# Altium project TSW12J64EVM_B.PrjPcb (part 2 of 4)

## Sheet TSW12J64EVM_B_4_ADC_IO.SchDoc
size 431 x 279 mm; Date: Not shown in title block; ApprovedBy: Not shown in title block; CheckedBy: Not shown in title block; Author: Not shown in title block; CompanyName: Not shown in title block; Engineer: Not shown in title block; Organization: Not shown in title block; Address1: Not shown in title block; Address2: Not shown in title block; Address3: Not shown in title block; Address4: Not shown in title block; DocumentNumber: 4; Revision: Use project parameter SCH_Rev; SheetNumber: 4; SheetTotal: 11; PageSetup: Record=PageOptions¦CenterHorizontal=True¦CenterVertical=True¦PrintScale=1.32¦XCorrection=1.00¦YCorrection=1.00¦PrintKind=0¦BorderSize=5000000¦LeftOffset=0¦BottomOffset=0¦Orientation=2¦PaperLength=1000¦PaperWidth=1000¦Scale=100¦PaperSource=15¦PrintQuality=600¦MediaType=1¦DitherType=10¦PaperKind=Letter¦PrintScaleMode=1
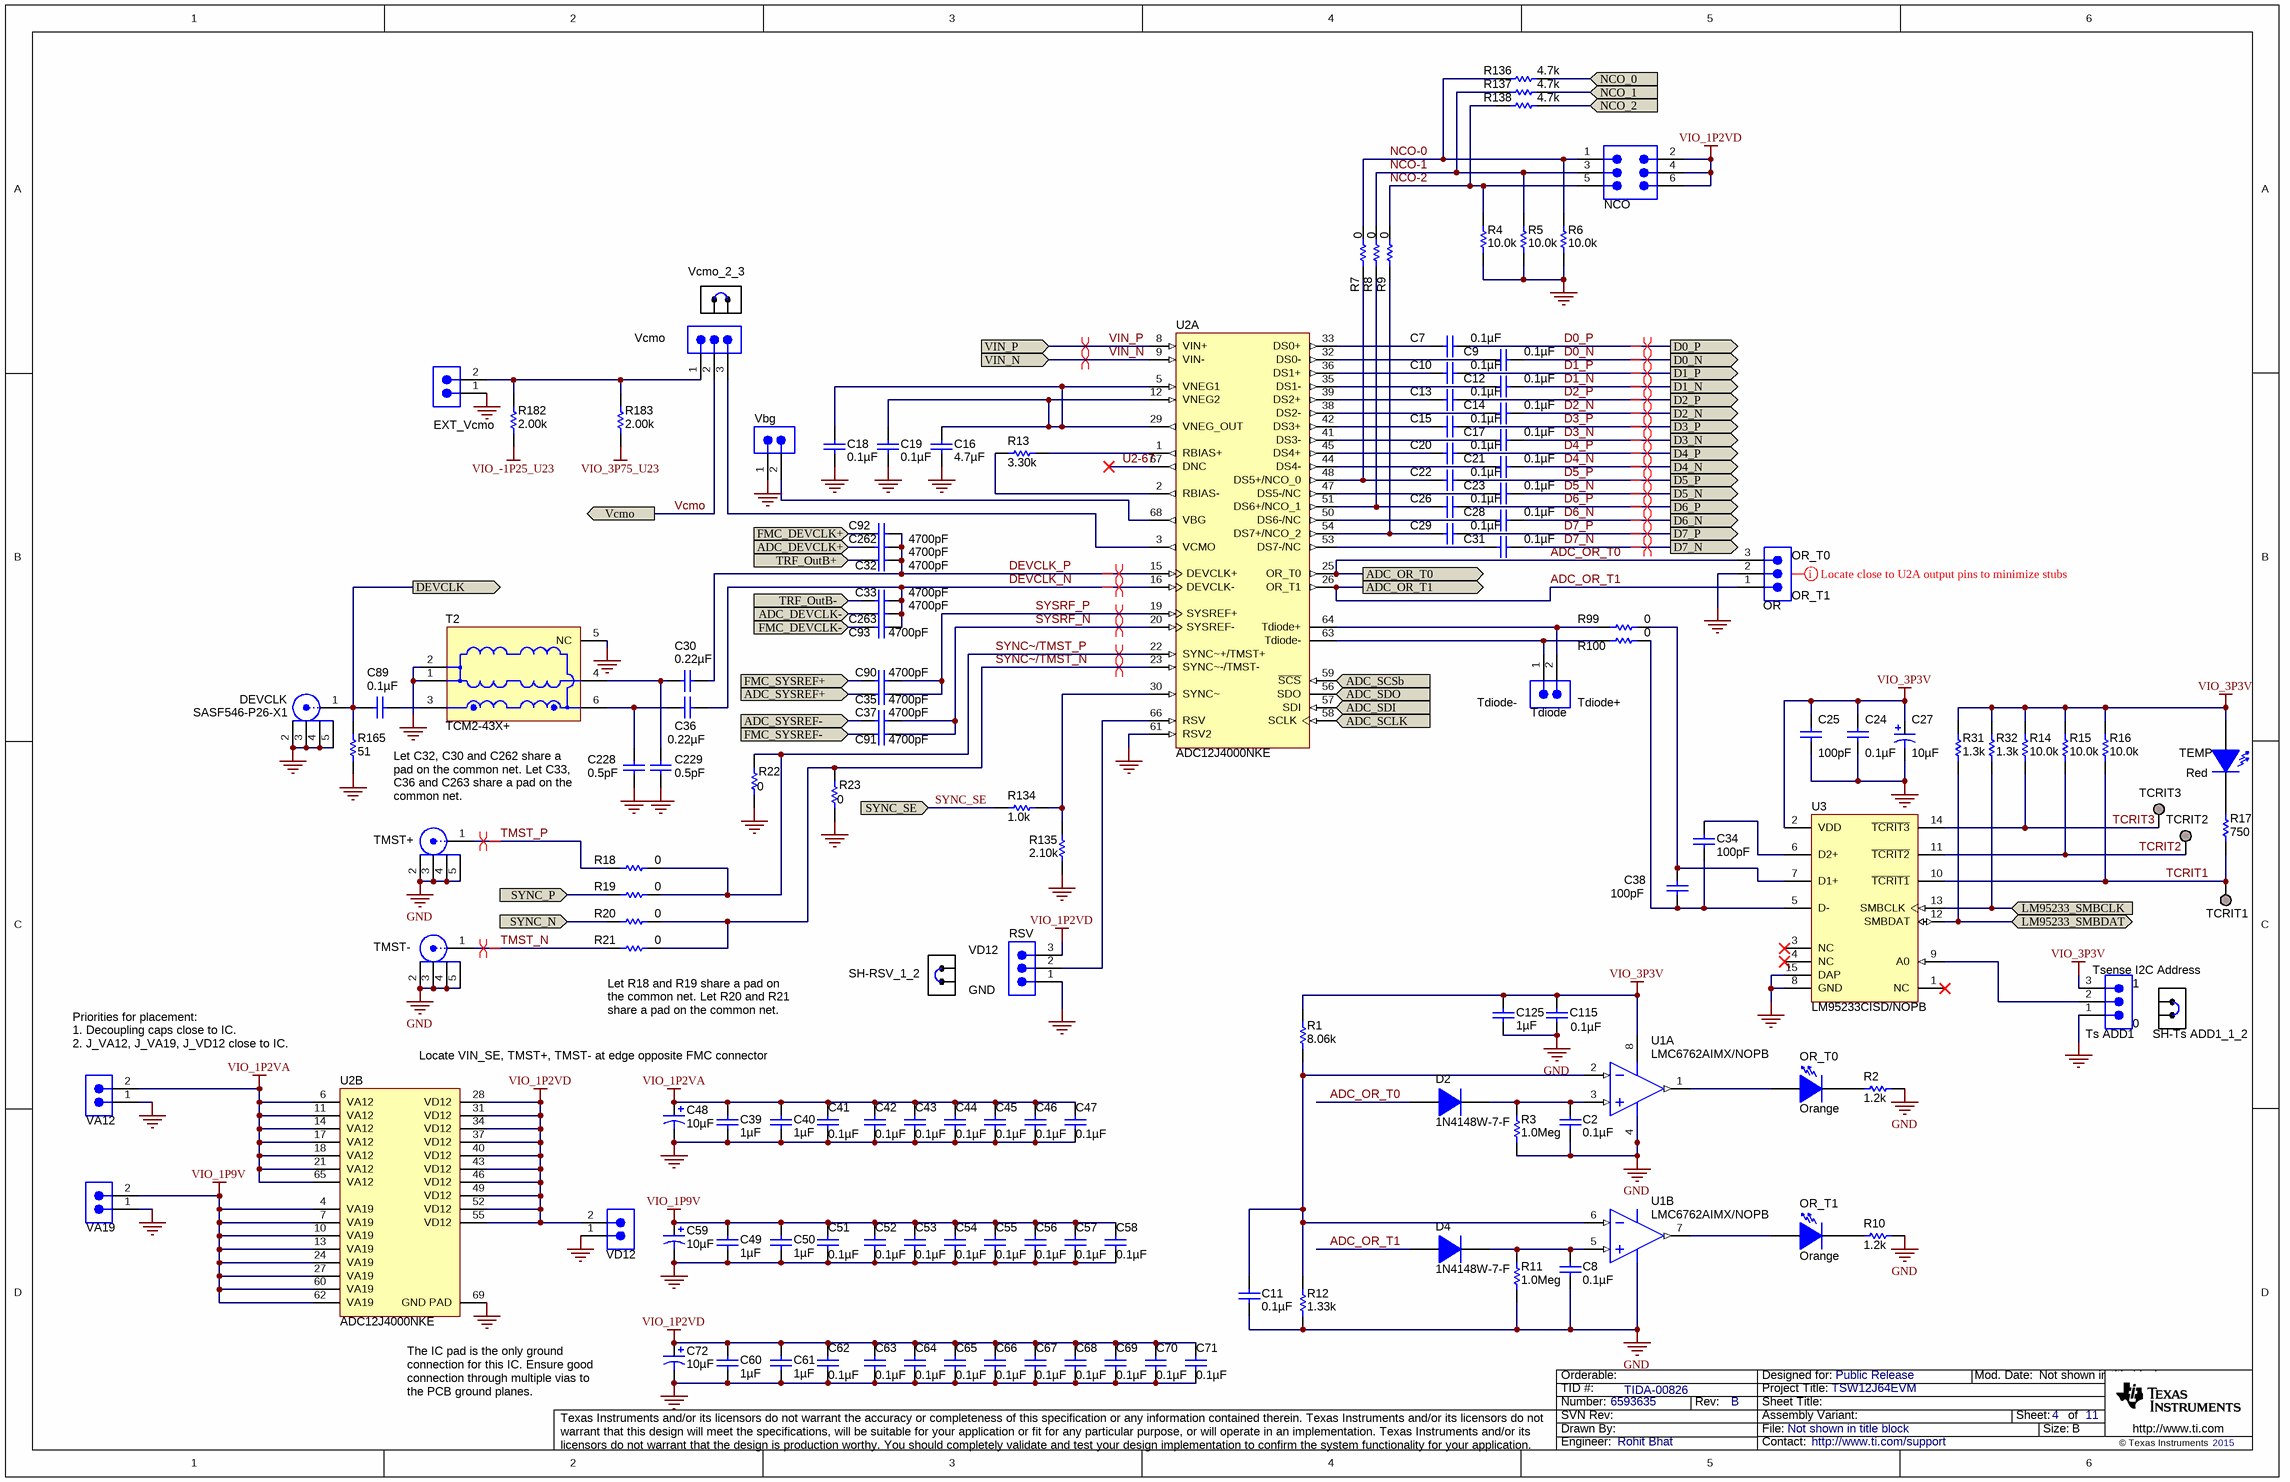
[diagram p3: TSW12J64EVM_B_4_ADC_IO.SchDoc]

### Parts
C2  ValueDisplayed: 0.1µF  [0402L]  (hidden comment: GRM155R71A104KA01D)
C7  ValueDisplayed: 0.1µF  [0201]  (hidden comment: C0603X5R0J104K)
C8  ValueDisplayed: 0.1µF  [0402L]  (hidden comment: GRM155R71A104KA01D)
C9  ValueDisplayed: 0.1µF  [0201]  (hidden comment: C0603X5R0J104K)
C10  ValueDisplayed: 0.1µF  [0201]  (hidden comment: C0603X5R0J104K)
C11  ValueDisplayed: 0.1µF  [0402L]  (hidden comment: GRM155R71A104KA01D)
C12  ValueDisplayed: 0.1µF  [0201]  (hidden comment: C0603X5R0J104K)
C13  ValueDisplayed: 0.1µF  [0201]  (hidden comment: C0603X5R0J104K)
C14  ValueDisplayed: 0.1µF  [0201]  (hidden comment: C0603X5R0J104K)
C15  ValueDisplayed: 0.1µF  [0201]  (hidden comment: C0603X5R0J104K)
C16  ValueDisplayed: 4.7µF  [0402L]  (hidden comment: C1005X5R0J475M050BC)
C17  ValueDisplayed: 0.1µF  [0201]  (hidden comment: C0603X5R0J104K)
C18  ValueDisplayed: 0.1µF  [0402L]  (hidden comment: C1005X5R1A104K)
C19  ValueDisplayed: 0.1µF  [0402L]  (hidden comment: C1005X5R1A104K)
C20  ValueDisplayed: 0.1µF  [0201]  (hidden comment: C0603X5R0J104K)
C21  ValueDisplayed: 0.1µF  [0201]  (hidden comment: C0603X5R0J104K)
C22  ValueDisplayed: 0.1µF  [0201]  (hidden comment: C0603X5R0J104K)
C23  ValueDisplayed: 0.1µF  [0201]  (hidden comment: C0603X5R0J104K)
C24  ValueDisplayed: 0.1µF  [0603L]  (hidden comment: 0603YC104JAT2A)
C25  ValueDisplayed: 100pF  [0603L]  (hidden comment: 06035A101JAT2A)
C26  ValueDisplayed: 0.1µF  [0201]  (hidden comment: C0603X5R0J104K)
C27  ValueDisplayed: 10µF  [3528-21]  (hidden comment: 293D106X0010B2TE3)
C28  ValueDisplayed: 0.1µF  [0201]  (hidden comment: C0603X5R0J104K)
C29  ValueDisplayed: 0.1µF  [0201]  (hidden comment: C0603X5R0J104K)
C30  ValueDisplayed: 0.22µF  [0201]  (hidden comment: C0603X5R0J224M)
C31  ValueDisplayed: 0.1µF  [0201]  (hidden comment: C0603X5R0J104K)
C32  ValueDisplayed: 4700pF  [0201]  (hidden comment: GRM033R61A472KA01D)
C33  ValueDisplayed: 4700pF  [0201]  (hidden comment: GRM033R61A472KA01D)
C34  ValueDisplayed: 100pF  [0603L]  (hidden comment: 06035A101JAT2A)
C35  ValueDisplayed: 4700pF  [0201]  (hidden comment: GRM033R61A472KA01D)
C36  ValueDisplayed: 0.22µF  [0201]  (hidden comment: C0603X5R0J224M)
C37  ValueDisplayed: 4700pF  [0201]  (hidden comment: GRM033R61A472KA01D)
C38  ValueDisplayed: 100pF  [0603L]  (hidden comment: 06035A101JAT2A)
C39  ValueDisplayed: 1µF  [0603L]  (hidden comment: C1608X5R1A105K)
C40  ValueDisplayed: 1µF  [0603L]  (hidden comment: C1608X5R1A105K)
C41  ValueDisplayed: 0.1µF  [0201]  (hidden comment: C0603X5R0J104K)
C42  ValueDisplayed: 0.1µF  [0201]  (hidden comment: C0603X5R0J104K)
C43  ValueDisplayed: 0.1µF  [0201]  (hidden comment: C0603X5R0J104K)
C44  ValueDisplayed: 0.1µF  [0201]  (hidden comment: C0603X5R0J104K)
C45  ValueDisplayed: 0.1µF  [0201]  (hidden comment: C0603X5R0J104K)
C46  ValueDisplayed: 0.1µF  [0201]  (hidden comment: C0603X5R0J104K)
C47  ValueDisplayed: 0.1µF  [0201]  (hidden comment: C0603X5R0J104K)
C48  ValueDisplayed: 10µF  [3528-21]  (hidden comment: 293D106X0010B2TE3)
C49  ValueDisplayed: 1µF  [0603L]  (hidden comment: C1608X5R1A105K)
C50  ValueDisplayed: 1µF  [0603L]  (hidden comment: C1608X5R1A105K)
C51  ValueDisplayed: 0.1µF  [0201]  (hidden comment: C0603X5R0J104K)
C52  ValueDisplayed: 0.1µF  [0201]  (hidden comment: C0603X5R0J104K)
C53  ValueDisplayed: 0.1µF  [0201]  (hidden comment: C0603X5R0J104K)
C54  ValueDisplayed: 0.1µF  [0201]  (hidden comment: C0603X5R0J104K)
C55  ValueDisplayed: 0.1µF  [0201]  (hidden comment: C0603X5R0J104K)
C56  ValueDisplayed: 0.1µF  [0201]  (hidden comment: C0603X5R0J104K)
C57  ValueDisplayed: 0.1µF  [0201]  (hidden comment: C0603X5R0J104K)
C58  ValueDisplayed: 0.1µF  [0201]  (hidden comment: C0603X5R0J104K)
C59  ValueDisplayed: 10µF  [3528-21]  (hidden comment: 293D106X0010B2TE3)
C60  ValueDisplayed: 1µF  [0603L]  (hidden comment: C1608X5R1A105K)
C61  ValueDisplayed: 1µF  [0603L]  (hidden comment: C1608X5R1A105K)
C62  ValueDisplayed: 0.1µF  [0201]  (hidden comment: C0603X5R0J104K)
C63  ValueDisplayed: 0.1µF  [0201]  (hidden comment: C0603X5R0J104K)
C64  ValueDisplayed: 0.1µF  [0201]  (hidden comment: C0603X5R0J104K)
C65  ValueDisplayed: 0.1µF  [0201]  (hidden comment: C0603X5R0J104K)
C66  ValueDisplayed: 0.1µF  [0201]  (hidden comment: C0603X5R0J104K)
C67  ValueDisplayed: 0.1µF  [0201]  (hidden comment: C0603X5R0J104K)
C68  ValueDisplayed: 0.1µF  [0201]  (hidden comment: C0603X5R0J104K)
C69  ValueDisplayed: 0.1µF  [0201]  (hidden comment: C0603X5R0J104K)
C70  ValueDisplayed: 0.1µF  [0201]  (hidden comment: C0603X5R0J104K)
C71  ValueDisplayed: 0.1µF  [0201]  (hidden comment: C0603X5R0J104K)
C72  ValueDisplayed: 10µF  [3528-21]  (hidden comment: 293D106X0010B2TE3)
C89  ValueDisplayed: 0.1µF  [0402L]  (hidden comment: C1005X5R1A104K)
C90  ValueDisplayed: 4700pF  [0201]  (hidden comment: GRM033R61A472KA01D)
C91  ValueDisplayed: 4700pF  [0201]  (hidden comment: GRM033R61A472KA01D)
C92  ValueDisplayed: 4700pF  [0201]  (hidden comment: GRM033R61A472KA01D)
C93  ValueDisplayed: 4700pF  [0201]  (hidden comment: GRM033R61A472KA01D)
C115  ValueDisplayed: 0.1µF  [0603L]  (hidden comment: 0603YC104JAT2A)
C125  ValueDisplayed: 1µF  [0603L]  (hidden comment: C1608X5R1A105K)
C228  ValueDisplayed: 0.5pF  [0402L]  (hidden comment: 500R07S0R5BV4T)
C229  ValueDisplayed: 0.5pF  [0402L]  (hidden comment: 500R07S0R5BV4T)
C262  ValueDisplayed: 4700pF  [0201]  (hidden comment: GRM033R61A472KA01D)
C263  ValueDisplayed: 4700pF  [0201]  (hidden comment: GRM033R61A472KA01D)
D2  1N4148W-7-F  [SOD-123]
D4  1N4148W-7-F  [SOD-123]
DEVCLK  SASF546-P26-X1  [CONN_LTI_SASF546-P26-X1]
EXT_Vcmo  TSW-102-07-G-S  [TSW-102-07-G-S]  (value not drawn)
NCO  TSW-103-07-G-D  [TSW-103-07-G-D]  (value not drawn)
OR  TSW-103-07-G-S  [TSW-103-07-G-S]  (value not drawn)
OR_T0  value Orange  [LED_LTST-C190]  (hidden comment: LTST-C190KFKT)
OR_T1  value Orange  [LED_LTST-C190]  (hidden comment: LTST-C190KFKT)
R1  value 8.06k  [0402L]  (hidden comment: CRCW04028K06FKED)
R2  value 1.2k  [0402L]  (hidden comment: CRCW04021K20JNED)
R3  value 1.0Meg  [0402L]  (hidden comment: CRCW04021M00JNED)
R4  value 10.0k  [0603L]  (hidden comment: CRCW060310K0FKEA)
R5  value 10.0k  [0603L]  (hidden comment: CRCW060310K0FKEA)
R6  value 10.0k  [0603L]  (hidden comment: CRCW060310K0FKEA)
R7  value 0  [0201]  (hidden comment: ERJ-1GE0R00C)
R8  value 0  [0201]  (hidden comment: ERJ-1GE0R00C)
R9  value 0  [0201]  (hidden comment: ERJ-1GE0R00C)
R10  value 1.2k  [0402L]  (hidden comment: CRCW04021K20JNED)
R11  value 1.0Meg  [0402L]  (hidden comment: CRCW04021M00JNED)
R12  value 1.33k  [0402L]  (hidden comment: CRCW04021K33FKED)
R13  value 3.30k  [0603L]  (hidden comment: RG1608P-332-B-T5)
R14  value 10.0k  [0603L]  (hidden comment: CRCW060310K0FKEA)
R15  value 10.0k  [0603L]  (hidden comment: CRCW060310K0FKEA)
R16  value 10.0k  [0603L]  (hidden comment: CRCW060310K0FKEA)
R17  value 750  [0603L]  (hidden comment: RC0603JR-07750RL)
R18  value 0  [0201]  (hidden comment: ERJ-1GE0R00C)
R19  value 0  [0201]  (hidden comment: ERJ-1GE0R00C)
R20  value 0  [0201]  (hidden comment: ERJ-1GE0R00C)
R21  value 0  [0201]  (hidden comment: ERJ-1GE0R00C)
R22  value 0  [0201]  (hidden comment: ERJ-1GE0R00C)
R23  value 0  [0201]  (hidden comment: ERJ-1GE0R00C)
R31  value 1.3k  [0603L]  (hidden comment: RC0603JR-071K3L)
R32  value 1.3k  [0603L]  (hidden comment: RC0603JR-071K3L)
R99  value 0  [0603L]  (hidden comment: ERJ-3GEY0R00V)
R100  value 0  [0603L]  (hidden comment: ERJ-3GEY0R00V)
R134  value 1.0k  [0603L]  (hidden comment: RC0603JR-071KL)
R135  value 2.10k  [0603L]  (hidden comment: CRCW06032K10FKEA)
R136  value 4.7k  [0603L]  (hidden comment: CRCW06034K70JNEA)
R137  value 4.7k  [0603L]  (hidden comment: CRCW06034K70JNEA)
R138  value 4.7k  [0603L]  (hidden comment: CRCW06034K70JNEA)
R165  value 51  [0402L]  (hidden comment: CRCW040251R0JNED)
R182  ValueDisplayed: 2.00k  [0402L]  (hidden comment: CRCW04022K00FKED)
R183  ValueDisplayed: 2.00k  [0402L]  (hidden comment: CRCW04022K00FKED)
RSV  TSW-103-07-G-S  [TSW-103-07-G-S]  (value not drawn)
SH-RSV_1_2  SNT-100-BK-G  [SNT-100-BK-G]  (value not drawn)
SH-Ts_ADD1_1_2  SNT-100-BK-G  [SNT-100-BK-G]  (value not drawn)
T2  TCM2-43X+  [Mini-Circuits-DB1627]
TCRIT1  TESTPOINT  [TESTPOINT]  (value not drawn)  (no BOM)
TCRIT2  TESTPOINT  [TESTPOINT]  (value not drawn)  (no BOM)
TCRIT3  TESTPOINT  [TESTPOINT]  (value not drawn)  (no BOM)
Tdiode  TSW-102-07-G-S  [TSW-102-07-G-S]  (value not drawn)
TEMP  value Red  [LED_LTST-C170]  (hidden comment: LTST-C170KRKT)
TMST+  142-0701-231  [Johnson_142-0701-231]  (value not drawn)
TMST-  142-0701-231  [Johnson_142-0701-231]  (value not drawn)
Ts_ADD1  TSW-103-07-G-S  [TSW-103-07-G-S]  (value not drawn)
U1  LMC6762AIMX/NOPB  [M08A_L]  (parts A,B of 2)
U2  ADC12J4000NKE  [RLY0068A]  (parts A,B of 2)
U3  LM95233CISD/NOPB  [SDA14B]
VA12  TSW-102-07-G-S  [TSW-102-07-G-S]  (value not drawn)
VA19  TSW-102-07-G-S  [TSW-102-07-G-S]  (value not drawn)
Vbg  TSW-102-07-G-S  [TSW-102-07-G-S]  (value not drawn)
Vcmo  TSW-103-07-G-S  [TSW-103-07-G-S]  (value not drawn)
Vcmo_2_3  SNT-100-BK-G  [SNT-100-BK-G]  (value not drawn)
VD12  TSW-102-07-G-S  [TSW-102-07-G-S]  (value not drawn)

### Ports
ADC_DEVCLK+ (in), ADC_DEVCLK- (in), ADC_OR_T0 (out), ADC_OR_T1 (out), ADC_SCLK (in), ADC_SCSb (in), ADC_SDI (in), ADC_SDO (out), ADC_SYSREF+, ADC_SYSREF-, D0_N (out), D0_P (out), D1_N (out), D1_P (out), D2_N (out), D2_P (out), D3_N (out), D3_P (out), D4_N (out), D4_P (out), D5_N (out), D5_P (out), D6_N (out), D6_P (out), D7_N (out), D7_P (out), DEVCLK (out), FMC_DEVCLK+ (in), FMC_DEVCLK- (in), FMC_SYSREF+, FMC_SYSREF-, LM95233_SMBCLK (in), LM95233_SMBDAT (bidir), NCO_0 (in), NCO_1 (in), NCO_2 (in), SYNC_N (in), SYNC_P (in), SYNC_SE (in), TRF_OutB+ (in), TRF_OutB- (in), Vcmo (out), VIN_N (in), VIN_P (in)

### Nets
GND: C2.2 C8.2 C11.2 C16.1 C18.1 C19.1 C24.2 C25.2 C27.2(-) C39.2 C40.2 C41.1 C42.1 C43.1 C44.1 C45.1 C46.1 C47.1 C48.2(-) C49.2 C50.2 C51.1 C52.1 C53.1 C54.1 C55.1 C56.1 C57.1 C58.1 C59.2(-) C60.2 C61.2 C62.1 C63.1 C64.1 C65.1 C66.1 C67.1 C68.1 C69.1 C70.1 C71.1 C72.2(-) C115.2 C125.2 C228.2 C229.2 DEVCLK.2 DEVCLK.3 DEVCLK.4 DEVCLK.5 EXT_Vcmo.1 OR.2 R2.2 R3.1 R4.1 R5.1 R6.1 R10.2 R11.1 R12.1 R22.2 R23.2 R135.1 R165.1 RSV.1 T2.1 T2.2 T2.5(NC) TMST+.2 TMST+.3 TMST+.4 TMST+.5 TMST-.2 TMST-.3 TMST-.4 TMST-.5 Ts_ADD1.1 U1.4(V-) U2.61(RSV2) U2.69(GND_PAD) U3.8(GND) U3.15(DAP) VA12.1 VA19.1 Vbg.1 VD12.1
VIO_1P2VA: C39.1 C40.1 C41.2 C42.2 C43.2 C44.2 C45.2 C46.2 C47.2 C48.1(+) U2.6(VA12) U2.11(VA12) U2.14(VA12) U2.17(VA12) U2.18(VA12) U2.21(VA12) U2.65(VA12) VA12.2
VIO_1P2VD: C60.1 C61.1 C62.2 C63.2 C64.2 C65.2 C66.2 C67.2 C68.2 C69.2 C70.2 C71.2 C72.1(+) NCO.2 NCO.4 NCO.6 RSV.3 U2.28(VD12) U2.31(VD12) U2.34(VD12) U2.37(VD12) U2.40(VD12) U2.43(VD12) U2.46(VD12) U2.49(VD12) U2.52(VD12) U2.55(VD12) VD12.2
VIO_1P9V: C49.1 C50.1 C51.2 C52.2 C53.2 C54.2 C55.2 C56.2 C57.2 C58.2 C59.1(+) U2.4(VA19) U2.7(VA19) U2.10(VA19) U2.13(VA19) U2.24(VA19) U2.27(VA19) U2.60(VA19) U2.62(VA19) VA19.2
VIO_3P3V: C24.1 C25.1 C27.1(+) C115.1 C125.1 R1.2 R14.2 R15.2 R16.2 R31.2 R32.2 TEMP.1(A) Ts_ADD1.3 U1.8(V+) U3.2(VDD)
VIO_3P75_U23: R183.1
VIO_-1P25_U23: R182.1
ADC_DEVCLK+: C262.2 ; port ADC_DEVCLK+
ADC_DEVCLK-: C263.2 ; port ADC_DEVCLK-
ADC_OR_T0: D2.2(A) OR.3 U2.25(OR_T0) ; port ADC_OR_T0
ADC_OR_T1: D4.2(A) OR.1 U2.26(OR_T1) ; port ADC_OR_T1
ADC_SCLK: U2.58(SCLK) ; port ADC_SCLK
ADC_SCSb: U2.59(~{SCS}) ; port ADC_SCSb
ADC_SDI: U2.57(SDI) ; port ADC_SDI
ADC_SDO: U2.56(SDO) ; port ADC_SDO
ADC_SYSREF+: C35.2 ; port ADC_SYSREF+
ADC_SYSREF-: C37.2 ; port ADC_SYSREF-
D0_N: C9.1 ; port D0_N
D0_P: C7.1 ; port D0_P
D1_N: C12.1 ; port D1_N
D1_P: C10.1 ; port D1_P
D2_N: C14.1 ; port D2_N
D2_P: C13.1 ; port D2_P
D3_N: C17.1 ; port D3_N
D3_P: C15.1 ; port D3_P
D4_N: C21.1 ; port D4_N
D4_P: C20.1 ; port D4_P
D5_N: C23.1 ; port D5_N
D5_P: C22.1 ; port D5_P
D6_N: C28.1 ; port D6_N
D6_P: C26.1 ; port D6_P
D7_N: C31.1 ; port D7_N
D7_P: C29.1 ; port D7_P
DEVCLK: C89.1 DEVCLK.1 R165.2 ; port DEVCLK
DEVCLK_N: C33.1 C36.1 C93.1 C263.1 U2.16(DEVCLK-)
DEVCLK_P: C30.1 C32.1 C92.1 C262.1 U2.15(DEVCLK+)
FMC_DEVCLK_N: C93.2 ; port FMC_DEVCLK-
FMC_DEVCLK_P: C92.2 ; port FMC_DEVCLK+
FMC_SYSREF_N: C91.2 ; port FMC_SYSREF-
FMC_SYSREF_P: C90.2 ; port FMC_SYSREF+
LM95233_SMBCLK: R32.1 U3.13(SMBCLK) ; port LM95233_SMBCLK
LM95233_SMBDAT: R31.1 U3.12(SMBDAT) ; port LM95233_SMBDAT
NCO-0: NCO.1 R6.2 R7.1 R136.1
NCO-1: NCO.3 R5.2 R8.1 R137.1
NCO-2: NCO.5 R4.2 R9.1 R138.1
NCO_0: R136.2 ; port NCO_0
NCO_1: R137.2 ; port NCO_1
NCO_2: R138.2 ; port NCO_2
SYNC_N: R20.2 ; port SYNC_N
SYNC_P: R19.2 ; port SYNC_P
SYNC_SE: R134.1 ; port SYNC_SE
SYNC~/TMST_N: R20.1 R21.1 R23.1 U2.23(SYNC~-/TMST-)
SYNC~/TMST_P: R18.1 R19.1 R22.1 U2.22(SYNC~+/TMST+)
SYSRF_N: C37.1 C91.1 U2.20(SYSREF-)
SYSRF_P: C35.1 C90.1 U2.19(SYSREF+)
TCRIT1: R16.1 R17.1 TCRIT1.1 U3.10(~{TCRIT1})
TCRIT2: R15.1 TCRIT2.1 U3.11(~{TCRIT2})
TCRIT3: R14.1 TCRIT3.1 U3.14(~{TCRIT3})
TMST_N: R21.2 TMST-.1
TMST_P: R18.2 TMST+.1
TRF_OutB_N: C33.2 ; port TRF_OutB-
TRF_OutB_P: C32.2 ; port TRF_OutB+
U2-67: U2.67(DNC)
Vcmo: Vcmo.2 ; port Vcmo
VIN_N: U2.9(VIN-) ; port VIN_N
VIN_P: U2.8(VIN+) ; port VIN_P
NetC2_1: C2.1 D2.1(K) R3.2 U1.3(INA+)
NetC7_2: C7.2 U2.33(DS0+)
NetC8_1: C8.1 D4.1(K) R11.2 U1.5(INB+)
NetC9_2: C9.2 U2.32(DS0-)
NetC10_2: C10.2 U2.36(DS1+)
NetC11_1: C11.1 R1.1 R12.2 U1.2(INA-) U1.6(INB-)
NetC12_2: C12.2 U2.35(DS1-)
NetC13_2: C13.2 U2.39(DS2+)
NetC14_2: C14.2 U2.38(DS2-)
NetC15_2: C15.2 U2.42(DS3+)
NetC16_2: C16.2 C18.2 C19.2 U2.5(VNEG1) U2.12(VNEG2) U2.29(VNEG_OUT)
NetC17_2: C17.2 U2.41(DS3-)
NetC20_2: C20.2 U2.45(DS4+)
NetC21_2: C21.2 U2.44(DS4-)
NetC22_2: C22.2 R7.2 U2.48(DS5+/NCO_0)
NetC23_2: C23.2 U2.47(DS5-/NC)
NetC26_2: C26.2 R8.2 U2.51(DS6+/NCO_1)
NetC28_2: C28.2 U2.50(DS6-/NC)
NetC29_2: C29.2 R9.2 U2.54(DS7+/NCO_2)
NetC30_2: C30.2 C229.1 T2.4
NetC31_2: C31.2 U2.53(DS7-/NC)
NetC34_1: C34.1 U3.6(D2+)
NetC34_2: C34.2 C38.2 R100.2 U3.5(D-)
NetC36_2: C36.2 C228.1 T2.6
NetC38_1: C38.1 R99.2 U3.7(D1+)
NetC89_2: C89.2 T2.3
NetEXT_Vcmo_2: EXT_Vcmo.2 R182.2 R183.2 Vcmo.1
NetOR_T0_1: OR_T0.1(A) U1.1(OUTA)
NetOR_T0_2: OR_T0.2(K) R2.1
NetOR_T1_1: OR_T1.1(A) U1.7(OUTB)
NetOR_T1_2: OR_T1.2(K) R10.1
NetR13_1: R13.1 U2.2(RBIAS-)
NetR13_2: R13.2 U2.1(RBIAS+)
NetR17_2: R17.2 TEMP.2(K)
NetR99_1: R99.1 Tdiode.2 U2.64(Tdiode+)
NetR100_1: R100.1 Tdiode.1 U2.63(Tdiode-)
NetR134_2: R134.2 R135.2 U2.30(SYNC~)
NetRSV_2: RSV.2 U2.66(RSV)
NetTs_ADD1_2: Ts_ADD1.2 U3.9(A0)
NetU2_3: U2.3(VCMO) Vcmo.3
NetU2_68: U2.68(VBG) Vbg.2

Not connected (* = marked no-connect by the designer): U3 1(NC)* 3(NC)* 4(NC)*

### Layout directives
differential pair: D0_N, D0_P, D1_N, D1_P, D2_N, D2_P, D3_N, D3_P, D4_N, D4_P, D5_N, D5_P, D6_N, D6_P, D7_N, D7_P, DEVCLK_N, DEVCLK_P, SYNC~/TMST_N, SYNC~/TMST_P, SYSRF_N, SYSRF_P, TMST_N, TMST_P, VIN_N, VIN_P
rule Undefined: (no net found under the mark)

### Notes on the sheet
- (near OR) OR_T0
- (near OR) OR_T1
- (near Tdiode) Tdiode-
- (near Tdiode) Tdiode+
- Let C32, C30 and C262 share a pad on the common net. Let C33, C36 and C263 share a pad on the common net.
- VD12
- (near Ts_ADD1) Tsense I2C Address
- (near R21) Let R18 and R19 share a pad on the common net. Let R20 and R21 share a pad on the common net.
- GND
- 1
- (near SH-Ts_ADD1_1_2) 0
- (near VA12) Priorities for placement:
  1. Decoupling caps close to IC.
  2. J_VA12, J_VA19, J_VD12 close to IC.
- Locate VIN_SE, TMST+, TMST- at edge opposite FMC connector
- (near U2) The IC pad is the only ground connection for this IC. Ensure good connection through multiple vias to the PCB ground planes.

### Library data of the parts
C2 C8 C11 = GRM155R71A104KA01D: CAP, CERM, 0.1uF, 10V, +/-10%, X7R, 0402; Manufacturer: MuRata; Polarized: N; CompType: Capacitor; U/M: EA; Cap_F: 0.0000001; Tolerance_%: 10; TaMin_C: -55; TaMax_C: 125; Cap_Case: 0402
C7 C9 C10 C12-C15 C17 C20-C23 C26 C28 C29 C31 C41-C47 C51-C58 C62-C71 = Capacitor: CAP, CERM, 0.1uF, 6.3V, X5R, 10%, 0201; Manufacturer: TDK; Polarized: N; U/M: EA
C16 = C1005X5R0J475M050BC: CAP, CERM, 4.7uF, 6.3V, +/-20%, X5R, 0402; Manufacturer: TDK; Polarized: N; CompType: Capacitor; U/M: EA; Cap_F: 0.0000047; Tolerance_%: 20; Value1: Unknown; VDC_V: 6.3; TaMin_C: -55; TaMax_C: 85; Cap_Case: 0402
C18 C19 C89 = C1005X5R1A104K: CAP, CERM, 0.1uF, 10V, +/-10%, X5R, 0402; Manufacturer: TDK; Polarized: N; CompType: Capacitor; U/M: EA; Cap_F: 0.0000001; Tolerance_%: 10; ESR_Ohm: 0.0186; Value1: 0.0186 ohm; TaMin_C: -55; TaMax_C: 85; Cap_Case: 0402
C24 C115 = 0603YC104JAT2A: CAP, CERM, 0.1uF, 16V, +/-5%, X7R, 0603; Manufacturer: AVX; Polarized: N; CompType: Capacitor; U/M: EA; Cap_F: 0.0000001; Tolerance_%: 5; ESR_Ohm: 0.039; Value1: 0.039 ohm; VDC_V: 16; TaMin_C: -55; TaMax_C: 125; Cap_Case: 0603
C25 C34 C38 = 06035A101JAT2A: CAP, CERM, 100pF, 50V, +/-5%, C0G/NP0, 0603; Manufacturer: AVX; Polarized: N; CompType: Capacitor; U/M: EA; Cap_F: 0.0000000001; Tolerance_%: 5; ESR_Ohm: 0.119; Value1: 0.119 ohm; VDC_V: 50; TaMin_C: -55; TaMax_C: 125; Cap_Case: 0603
C27 C48 C59 C72 = 293D106X0010B2TE3: CAP, TANT, 10uF, 10V, +/-20%, 2.5 ohm, 3528-21 SMD; Manufacturer: Vishay-Sprague; Polarized: Y; CompType: Capacitor; U/M: EA; Cap_F: 0.00001; Tolerance_%: 20; Value1: 2.5 ohm; VDC_V: 10; ESR_Ohm: 2.5; IRMS_A: 0.18; TaMin_C: -55; TaMax_C: 125; Cap_Case: B
C30 C36 = C0603X5R0J224M: CAP, CERM, 0.22uF, 6.3V, +/-20%, X5R, 0201; Manufacturer: TDK; Polarized: N; CompType: Capacitor; U/M: EA; Cap_F: 0.00000022; Tolerance_%: 20; Value1: Unknown; VDC_V: 6.3; TaMin_C: -55; TaMax_C: 85
C32 C33 C35 C37 C90-C93 C262 C263 = GRM033R61A472KA01D: CAP, CERM, 4700pF, 10V, +/-10%, X5R, 0201; Manufacturer: MuRata; Polarized: N; CompType: Capacitor; U/M: EA; Cap_F: 0.0000000047; Tolerance_%: 10; TaMin_C: -55; TaMax_C: 85
C39 C40 C49 C50 C60 C61 C125 = C1608X5R1A105K: CAP, CERM, 1uF, 10V, +/-10%, X5R, 0603; Manufacturer: TDK; Polarized: N; CompType: Capacitor; U/M: EA; Cap_F: 0.000001; Tolerance_%: 10; ESR_Ohm: 0.0057; Value1: 0.0057 ohm; TaMin_C: -55; TaMax_C: 85; Cap_Case: 0603
C228 C229 = GRM155R71A104KA01D: CAP CER 0.5PF 50V NP0 0402; Manufacturer: Johanson Technology Inc; Polarized: N; CompType: Capacitor; U/M: EA; VDC_V: 50; Cap_Case: 0402
D2 D4 = 1N4148W-7-F: Diode, Ultrafast, 100V, 0.15A, SOD-123; Manufacturer: Diodes Inc.; U/M: EA; Vf_V: 1.25; Io_A: 0.15; Vr_V: 100; TJmax_C: 150; Value: 1.25V
DEVCLK = SASF546-P26-X1: Connector, SMA,Vertical, Thru hole w/SMT center pin; Manufacturer: Lighthorse Technologies; U/M: EA
EXT_Vcmo Tdiode VA12 VA19 Vbg VD12 = TSW-102-07-G-S: Header, TH, 100mil, 2x1, Gold plated, 230 mil above insulator; Manufacturer: Samtec, Inc.; U/M: EA
NCO = TSW-103-07-G-D: Header, TH, 100mil, 3x2, Gold plated, 230 mil above insulator; Manufacturer: Samtec, Inc.; Alternate Manufacturer: Any; Alternate PartNumber: Equivalent; U/M: EA
OR RSV Ts_ADD1 Vcmo = TSW-103-07-G-S: Header, TH, 100mil, 3x1, Gold plated, 230 mil above insulator; Manufacturer: Samtec, Inc.; Alternate Manufacturer: Any; Alternate PartNumber: Equivalent; U/M: EA
OR_T0 OR_T1 = LTST-C190KFKT: LED, Orange, SMD; Manufacturer: Lite-On; Vf_V: 2; Value2: 2V; Io_A: 0.02; Power_TotalModule: 0.075; Value1: 0.075W; U/M: EA
R1 = CRCW04028K06FKED: RES, 8.06k ohm, 1%, 0.063W, 0402; Manufacturer: Vishay-Dale; CompType: Resistor; Res_ohm: 8060; Value_Code: 8k06; Tolerance_%: 1; Power_W: 0.063; VDC_V: 50; TempCo: 100 ppm/C; EIA_Code: E96; U/M: EA
R2 R10 = CRCW04021K20JNED: RES, 1.2k ohm, 5%, 0.063W, 0402; Manufacturer: Vishay-Dale; CompType: Resistor; Res_ohm: 1200; Value_Code: 1k20; Tolerance_%: 5; Power_W: 0.063; VDC_V: 50; TempCo: 200 ppm/C; EIA_Code: E24; U/M: EA
R3 R11 = CRCW04021M00JNED: RES, 1.0Meg ohm, 5%, 0.063W, 0402; Manufacturer: Vishay-Dale; CompType: Resistor; Res_ohm: 1000000; Value_Code: 1M00; Tolerance_%: 5; Power_W: 0.063; VDC_V: 50; TempCo: 200 ppm/C; EIA_Code: E24; U/M: EA
R4-R6 R14-R16 = CRCW060310K0FKEA: RES, 10.0k ohm, 1%, 0.1W, 0603; Manufacturer: Vishay-Dale; CompType: Resistor; Res_ohm: 10000; Value_Code: 10k0; Tolerance_%: 1; Power_W: 0.1; VDC_V: 75; TempCo: 100 ppm/C; EIA_Code: E96; U/M: EA
R7-R9 R18-R23 = ERJ-1GE0R00C: RES, 0 ohm, 5%, 0.05W, 0201; Manufacturer: Panasonic; CompType: Resistor; Value_Code: 0000; Tolerance_%: 5; Power_W: 0.05; VDC_V: 15; TempCo: 600 ppm/C; EIA_Code: E24; U/M: EA
R12 = CRCW04021K33FKED: RES, 1.33k ohm, 1%, 0.063W, 0402; Manufacturer: Vishay-Dale; CompType: Resistor; Res_ohm: 1330; Value_Code: 1k33; Tolerance_%: 1; Power_W: 0.063; VDC_V: 50; TempCo: 100 ppm/C; EIA_Code: E96; U/M: EA
R13 = RG1608P-332-B-T5: RES, 3.30k ohm, 0.1%, 0.1W, 0603; Manufacturer: Susumu Co Ltd; CompType: Resistor; Res_ohm: 3300; Value_Code: 3k30; Tolerance_%: 0.1; VDC_V: 75; TempCo: 25 ppm/C; U/M: EA
R17 = RC0603JR-07750RL: RES, 750 ohm, 5%, 0.1W, 0603; Manufacturer: Yageo America; CompType: Resistor; Value_Code: 750R; Tolerance_%: 5; Power_W: 0.1; VDC_V: 50; TempCo: 100 ppm/C; EIA_Code: E24; U/M: EA
R31 R32 = RC0603JR-071K3L: RES, 1.3k ohm, 5%, 0.1W, 0603; Manufacturer: Yageo America; CompType: Resistor; Res_ohm: 1300; Value_Code: 1k30; Tolerance_%: 5; Power_W: 0.1; VDC_V: 50; TempCo: 100 ppm/C; EIA_Code: E24; U/M: EA
R99 R100 = ERJ-3GEY0R00V: RES, 0 ohm, 5%, 0.1W, 0603; Manufacturer: Panasonic; CompType: Resistor; Value_Code: 0000; Tolerance_%: 5; Power_W: 0.1; VDC_V: 50; TempCo: 600 ppm/C; EIA_Code: E24; U/M: EA
R134 = RC0603JR-071KL: RES, 1.0k ohm, 5%, 0.1W, 0603; Manufacturer: Yageo America; CompType: Resistor; Res_ohm: 1000; Value_Code: 1k00; Tolerance_%: 5; Power_W: 0.1; VDC_V: 50; TempCo: 100 ppm/C; EIA_Code: E24; U/M: EA
R135 = CRCW06032K10FKEA: RES, 2.10k ohm, 1%, 0.1W, 0603; Manufacturer: Vishay-Dale; CompType: Resistor; Res_ohm: 2100; Value_Code: 2k10; Tolerance_%: 1; Power_W: 0.1; VDC_V: 75; TempCo: 100 ppm/C; EIA_Code: E96; U/M: EA
R136-R138 = CRCW06034K70JNEA: RES, 4.7k ohm, 5%, 0.1W, 0603; Manufacturer: Vishay-Dale; CompType: Resistor; Res_ohm: 4700; Value_Code: 4k70; Tolerance_%: 5; Power_W: 0.1; VDC_V: 75; TempCo: 200 ppm/C; EIA_Code: E24; U/M: EA
R165 = CRCW040251R0JNED: RES, 51 ohm, 5%, 0.063W, 0402; Manufacturer: Vishay-Dale; Alternate Manufacturer: Any; Alternate PartNumber: Equivalent; CompType: Resistor; Value_Code: 51R0; Tolerance_%: 5; Power_W: 0.063; VDC_V: 50; TempCo: 200 ppm/C; EIA_Code: E24; U/M: EA
R182 R183 = CRCW04022K00FKED: RES, 2.00 k, 1%, 0.063 W, 0402; Manufacturer: Vishay-Dale; CompType: Resistor; Value: 2.00k; Res_ohm: 2000; Value_Code: 2k00; Tolerance_%: 1; Power_W: 0.063; Value2: 0.063W; VDC_V: 50; TempCo: 100 ppm/C; EIA_Code: E96; U/M: EA
SH-RSV_1_2 SH-Ts_ADD1_1_2 Vcmo_2_3 = SNT-100-BK-G: Shunt, 100mil, Gold plated, Black; Manufacturer: Samtec, Inc.; Alternate Manufacturer: 3M; Alternate PartNumber: 969102-0000-DA; Value: 1x2; Note: You can "mate" this to a header by matching the designator.  i.e. use SH-J3 for header J3
T2 = TCM2-43X+: Transformer, RF, 50 ohm, 10 to 4000 MHz, SMT; Manufacturer: Minicircuits; SymbolCreator: a0799628; U/M: EA
TCRIT1-TCRIT3 = TESTPOINT: TEST POINT.  No entry in BOM.
TEMP = LTST-C170KRKT: LED, Red, SMD; Manufacturer: Lite-On; Vf_V: 2; Value2: 2V; Io_A: 20; Value1: W; U/M: EA
TMST+ TMST- = 142-0701-231: Connector, TH, SMA; Manufacturer: Emerson Network Power; SymbolCreator: X0208326; U/M: EA
U1 = LMC6762AIMX: Dual Micro-Power Rail-to-Rail Input CMOS Comparator with Push-Pull Output, 8-pin Narrow SOIC; Manufacturer: Texas Instruments; PackageTopMarking: NSZXTT*LMC67*62AIM; PowerWise: N
U2 = ADC12X3500RFLQNOPB: ADC12J4000RLY Ultra-Wideband RF Sampling Subsystem, RLY0068A; Alternate Manufacturer: None; Manufacturer: Texas Instruments; SymbolCreator: a0411947; CompType: IC; U/M: EA
U3 = LM95233CISD/NOPB: Dual Remote Diode and Local Temperature Sensor with SMBus Interface and TruTherm Technology, 14-pin LLP, Pb-Free; Manufacturer: Texas Instruments; PackageTopMarking: NS*UZXYTT*95233CI; PowerWise: Y; CompType: Temp Sensor IC

## Sheet TSW12J64EVM_B_5_FMC.SchDoc
size 558 x 431 mm; Date: Not shown in title block; ApprovedBy: Not shown in title block; CheckedBy: Not shown in title block; Author: Not shown in title block; CompanyName: Not shown in title block; Engineer: Not shown in title block; Organization: Not shown in title block; Address1: Not shown in title block; Address2: Not shown in title block; Address3: Not shown in title block; Address4: Not shown in title block; DocumentNumber: 5; Revision: Use project parameter SCH_Rev; SheetNumber: 5; SheetTotal: 11; PageSetup: Record=PageOptions¦CenterHorizontal=True¦CenterVertical=True¦PrintScale=0.62¦XCorrection=1.00¦YCorrection=1.00¦PrintKind=0¦BorderSize=5000000¦LeftOffset=0¦BottomOffset=0¦Orientation=2¦PaperLength=1000¦PaperWidth=1000¦Scale=100¦PaperSource=15¦PrintQuality=600¦MediaType=1¦DitherType=10¦PaperKind=11x17¦PrintScaleMode=1
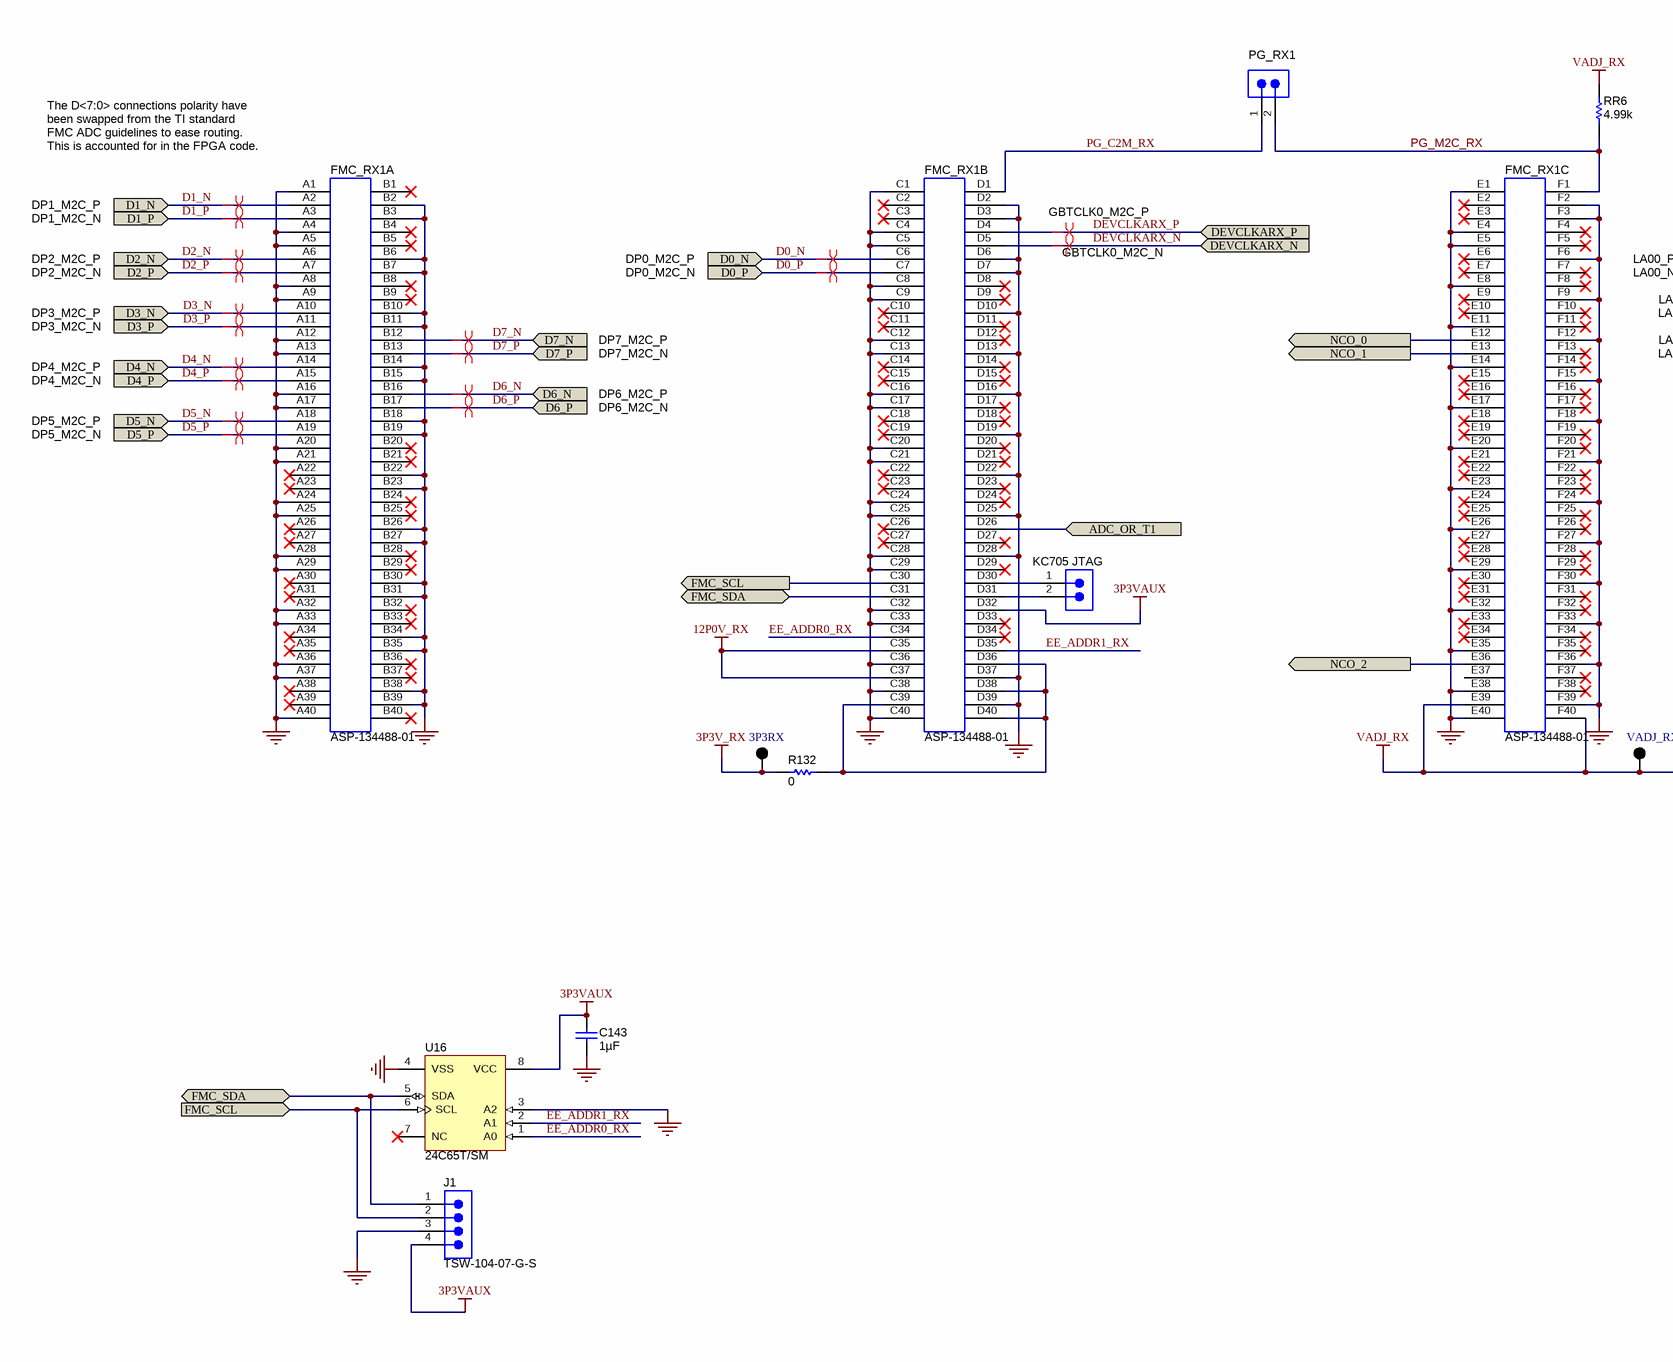
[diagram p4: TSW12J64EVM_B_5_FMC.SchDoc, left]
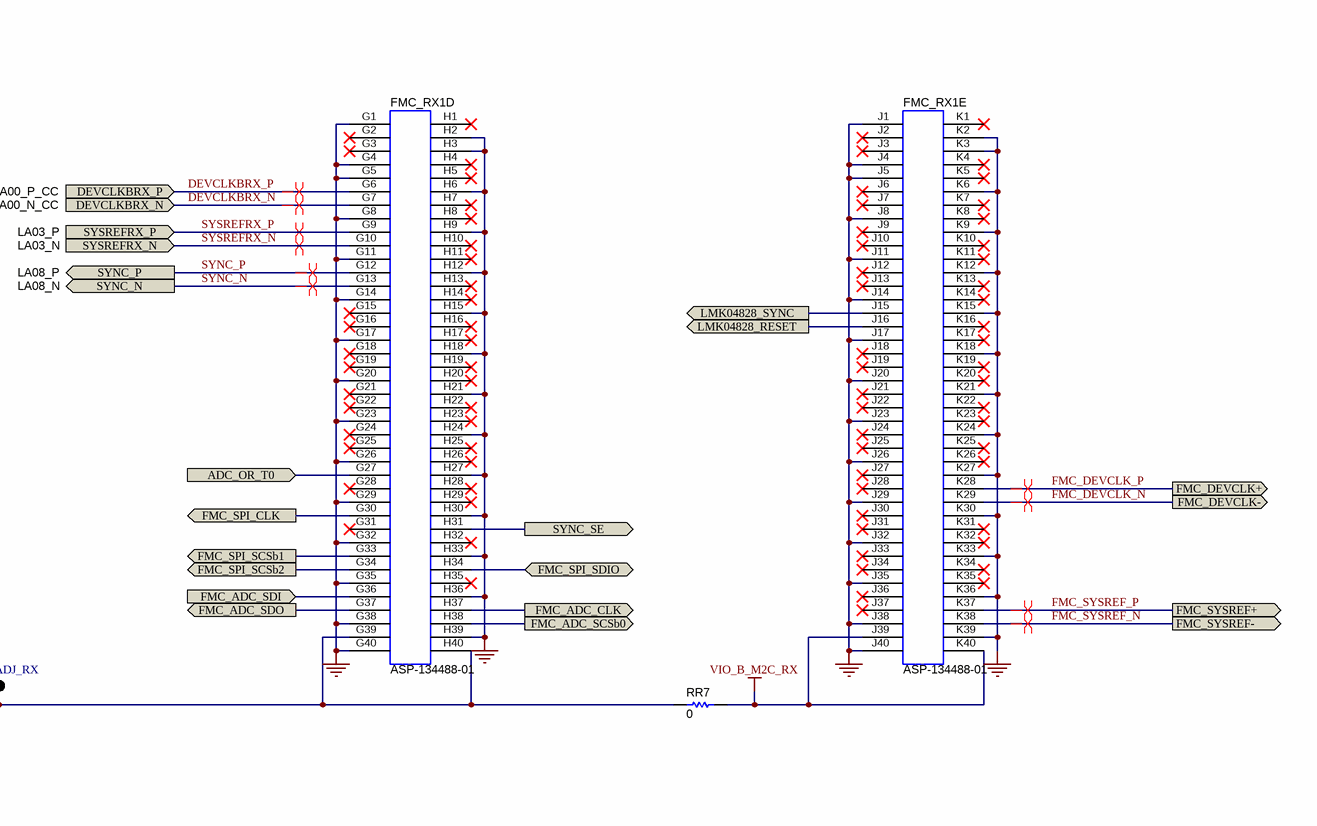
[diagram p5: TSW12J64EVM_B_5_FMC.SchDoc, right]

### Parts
3P3RX  5011  [Keystone5011]  (value not drawn)
C143  ValueDisplayed: 1µF  [0603L]  (hidden comment: C1608X5R1A105K)
FMC_RX1  ASP-134488-01  [CONN_SEARAY_ASP-134488-01]  (parts A,B,C,D,E of 5)
J1  TSW-104-07-G-S  [TSW-104-07-G-S]
KC705_JTAG  TSW-102-07-G-S  [TSW-102-07-G-S]  (value not drawn)
PG_RX1  TSW-102-07-G-S  [TSW-102-07-G-S]  (value not drawn)
R132  value 0  [0603L]  (hidden comment: CRCW06030000Z0EA)
RR6  value 4.99k  [0603L]  (hidden comment: CRCW06034K99FKEA)
RR7  value 0  [0603L]  (hidden comment: ERJ-3GEY0R00V)
U16  24C65T/SM  [SOIJ-SM8_N]
VADJ_RX  5011  [Keystone5011]  (value not drawn)

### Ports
ADC_OR_T0 (in), ADC_OR_T1 (in), D0_N (in), D0_P (in), D1_N (in), D1_P (in), D2_N (in), D2_P (in), D3_N (in), D3_P (in), D4_N (in), D4_P (in), D5_N (in), D5_P (in), D6_N (in), D6_P (in), D7_N (in), D7_P (in), DEVCLKARX_N (in), DEVCLKARX_P (in), DEVCLKBRX_N (in), DEVCLKBRX_P (in), FMC_ADC_CLK (out), FMC_ADC_SCSb0 (out), FMC_ADC_SDI (in), FMC_ADC_SDO (out), FMC_DEVCLK+ (out), FMC_DEVCLK- (out), FMC_SCL (in), FMC_SCL (out), FMC_SDA (bidir), FMC_SPI_CLK (out), FMC_SPI_SCSb1 (out), FMC_SPI_SCSb2 (out), FMC_SPI_SDIO (bidir), FMC_SYSREF+, FMC_SYSREF-, LMK04828_RESET (out), LMK04828_SYNC (out), NCO_0 (out), NCO_1 (out), NCO_2 (out), SYNC_N (out), SYNC_P (out), SYNC_SE (out), SYSREFRX_N (in), SYSREFRX_P (in)

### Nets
3P3V_RX: 3P3RX.1 R132.1
3P3VAUX: C143.1 FMC_RX1.D32 J1.4 U16.8(VCC)
12P0V_RX: FMC_RX1.C35 FMC_RX1.C37
GND: C143.2 FMC_RX1.A1 FMC_RX1.A4 FMC_RX1.A5 FMC_RX1.A8 FMC_RX1.A9 FMC_RX1.A12 FMC_RX1.A13 FMC_RX1.A16 FMC_RX1.A17 FMC_RX1.A20 FMC_RX1.A21 FMC_RX1.A24 FMC_RX1.A25 FMC_RX1.A28 FMC_RX1.A29 FMC_RX1.A32 FMC_RX1.A33 FMC_RX1.A36 FMC_RX1.A37 FMC_RX1.A40 FMC_RX1.B2 FMC_RX1.B3 FMC_RX1.B6 FMC_RX1.B7 FMC_RX1.B10 FMC_RX1.B11 FMC_RX1.B14 FMC_RX1.B15 FMC_RX1.B18 FMC_RX1.B19 FMC_RX1.B22 FMC_RX1.B23 FMC_RX1.B26 FMC_RX1.B27 FMC_RX1.B30 FMC_RX1.B31 FMC_RX1.B34 FMC_RX1.B35 FMC_RX1.B38 FMC_RX1.B39 FMC_RX1.C1 FMC_RX1.C4 FMC_RX1.C5 FMC_RX1.C8 FMC_RX1.C9 FMC_RX1.C12 FMC_RX1.C13 FMC_RX1.C16 FMC_RX1.C17 FMC_RX1.C20 FMC_RX1.C21 FMC_RX1.C24 FMC_RX1.C25 FMC_RX1.C28 FMC_RX1.C29 FMC_RX1.C32 FMC_RX1.C33 FMC_RX1.C36 FMC_RX1.C38 FMC_RX1.C40 FMC_RX1.D2 FMC_RX1.D3 FMC_RX1.D6 FMC_RX1.D7 FMC_RX1.D10 FMC_RX1.D13 FMC_RX1.D16 FMC_RX1.D19 FMC_RX1.D22 FMC_RX1.D25 FMC_RX1.D28 FMC_RX1.D37 FMC_RX1.D39 FMC_RX1.E1 FMC_RX1.E4 FMC_RX1.E5 FMC_RX1.E8 FMC_RX1.E11 FMC_RX1.E14 FMC_RX1.E17 FMC_RX1.E20 FMC_RX1.E23 FMC_RX1.E26 FMC_RX1.E29 FMC_RX1.E32 FMC_RX1.E35 FMC_RX1.E38 FMC_RX1.E40 FMC_RX1.F2 FMC_RX1.F3 FMC_RX1.F6 FMC_RX1.F9 FMC_RX1.F12 FMC_RX1.F15 FMC_RX1.F18 FMC_RX1.F21 FMC_RX1.F24 FMC_RX1.F27 FMC_RX1.F30 FMC_RX1.F33 FMC_RX1.F36 FMC_RX1.F39 FMC_RX1.G1 FMC_RX1.G4 FMC_RX1.G5 FMC_RX1.G8 FMC_RX1.G11 FMC_RX1.G14 FMC_RX1.G17 FMC_RX1.G20 FMC_RX1.G23 FMC_RX1.G26 FMC_RX1.G29 FMC_RX1.G32 FMC_RX1.G35 FMC_RX1.G38 FMC_RX1.G40 FMC_RX1.H2 FMC_RX1.H3 FMC_RX1.H6 FMC_RX1.H9 FMC_RX1.H12 FMC_RX1.H15 FMC_RX1.H18 FMC_RX1.H21 FMC_RX1.H24 FMC_RX1.H27 FMC_RX1.H30 FMC_RX1.H33 FMC_RX1.H36 FMC_RX1.H39 FMC_RX1.J1 FMC_RX1.J4 FMC_RX1.J5 FMC_RX1.J8 FMC_RX1.J11 FMC_RX1.J14 FMC_RX1.J17 FMC_RX1.J20 FMC_RX1.J23 FMC_RX1.J26 FMC_RX1.J29 FMC_RX1.J32 FMC_RX1.J35 FMC_RX1.J38 FMC_RX1.J40 FMC_RX1.K2 FMC_RX1.K3 FMC_RX1.K6 FMC_RX1.K9 FMC_RX1.K12 FMC_RX1.K15 FMC_RX1.K18 FMC_RX1.K21 FMC_RX1.K24 FMC_RX1.K27 FMC_RX1.K30 FMC_RX1.K33 FMC_RX1.K36 FMC_RX1.K39 J1.3 U16.3(A2) U16.4(VSS)
VADJ_RX: FMC_RX1.E39 FMC_RX1.F40 FMC_RX1.G39 FMC_RX1.H40 RR6.2 RR7.1 VADJ_RX.1
VIO_B_M2C_RX: FMC_RX1.J39 FMC_RX1.K40 RR7.2
ADC_OR_T0: FMC_RX1.G27 ; port ADC_OR_T0
ADC_OR_T1: FMC_RX1.D26 ; port ADC_OR_T1
D0_N: FMC_RX1.C6 ; port D0_N
D0_P: FMC_RX1.C7 ; port D0_P
D1_N: FMC_RX1.A2 ; port D1_N
D1_P: FMC_RX1.A3 ; port D1_P
D2_N: FMC_RX1.A6 ; port D2_N
D2_P: FMC_RX1.A7 ; port D2_P
D3_N: FMC_RX1.A10 ; port D3_N
D3_P: FMC_RX1.A11 ; port D3_P
D4_N: FMC_RX1.A14 ; port D4_N
D4_P: FMC_RX1.A15 ; port D4_P
D5_N: FMC_RX1.A18 ; port D5_N
D5_P: FMC_RX1.A19 ; port D5_P
D6_N: FMC_RX1.B16 ; port D6_N
D6_P: FMC_RX1.B17 ; port D6_P
D7_N: FMC_RX1.B12 ; port D7_N
D7_P: FMC_RX1.B13 ; port D7_P
DEVCLKARX_N: FMC_RX1.D5 ; port DEVCLKARX_N
DEVCLKARX_P: FMC_RX1.D4 ; port DEVCLKARX_P
DEVCLKBRX_N: FMC_RX1.G7 ; port DEVCLKBRX_N
DEVCLKBRX_P: FMC_RX1.G6 ; port DEVCLKBRX_P
EE_ADDR0_RX: FMC_RX1.C34 U16.1(A0)
EE_ADDR1_RX: FMC_RX1.D35 U16.2(A1)
FMC_ADC_CLK: FMC_RX1.H37 ; port FMC_ADC_CLK
FMC_ADC_SCSb0: FMC_RX1.H38 ; port FMC_ADC_SCSb0
FMC_ADC_SDI: FMC_RX1.G36 ; port FMC_ADC_SDI
FMC_ADC_SDO: FMC_RX1.G37 ; port FMC_ADC_SDO
FMC_DEVCLK_N: FMC_RX1.K29 ; port FMC_DEVCLK-
FMC_DEVCLK_P: FMC_RX1.K28 ; port FMC_DEVCLK+
FMC_SCL: FMC_RX1.C30 J1.2 U16.6(SCL) ; port FMC_SCL
FMC_SDA: FMC_RX1.C31 J1.1 U16.5(SDA) ; port FMC_SDA
FMC_SPI_CLK: FMC_RX1.G30 ; port FMC_SPI_CLK
FMC_SPI_SCSb1: FMC_RX1.G33 ; port FMC_SPI_SCSb1
FMC_SPI_SCSb2: FMC_RX1.G34 ; port FMC_SPI_SCSb2
FMC_SPI_SDIO: FMC_RX1.H34 ; port FMC_SPI_SDIO
FMC_SYSREF_N: FMC_RX1.K38 ; port FMC_SYSREF-
FMC_SYSREF_P: FMC_RX1.K37 ; port FMC_SYSREF+
LMK04828_RESET: FMC_RX1.J16 ; port LMK04828_RESET
LMK04828_SYNC: FMC_RX1.J15 ; port LMK04828_SYNC
NCO_0: FMC_RX1.E12 ; port NCO_0
NCO_1: FMC_RX1.E13 ; port NCO_1
NCO_2: FMC_RX1.E36 ; port NCO_2
PG_C2M_RX: FMC_RX1.D1 PG_RX1.1
PG_M2C_RX: FMC_RX1.F1 PG_RX1.2 RR6.1
SYNC_N: FMC_RX1.G13 ; port SYNC_N
SYNC_P: FMC_RX1.G12 ; port SYNC_P
SYNC_SE: FMC_RX1.H31 ; port SYNC_SE
SYSREFRX_N: FMC_RX1.G10 ; port SYSREFRX_N
SYSREFRX_P: FMC_RX1.G9 ; port SYSREFRX_P
NetFMC_RX1_C39: FMC_RX1.C39 FMC_RX1.D36 FMC_RX1.D38 FMC_RX1.D40 R132.2
NetFMC_RX1_D30: FMC_RX1.D30 KC705_JTAG.1
NetFMC_RX1_D31: FMC_RX1.D31 KC705_JTAG.2

Not connected (* = marked no-connect by the designer): FMC_RX1 A22* A23* A26* A27* A30* A31* A34* A35* A38* A39* B1* B4* B5* B8* B9* B20* B21* B24* B25* B28* B29* B32* B33* B36* B37* B40* C2* C3* C10* C11* C14* C15* C18* C19* C22* C23* C26* C27* D8* D9* D11* D12* D14* D15* D17* D18* D20* D21* D23* D24* D27* D29* D33* D34* E2* E3* E6* E7* E9* E10* E15* E16* E18* E19* E21* E22* E24* E25* E27* E28* E30* E31* E33* E34* E37 F4* F5* F7* F8* F10* F11* F13* F14* F16* F17* F19* F20* F22* F23* F25* F26* F28* F29* F31* F32* F34* F35* F37* F38* G2* G3* G15* G16* G18* G19* G21* G22* G24* G25* G28* G31* H1* H4* H5* H7* H8* H10* H11* H13* H14* H16* H17* H19* H20* H22* H23* H25* H26* H28* H29* H32* H35* J2* J3* J6* J7* J9* J10* J12* J13* J18* J19* J21* J22* J24* J25* J27* J28* J30* J31* J33* J34* J36* J37* K1* K4* K5* K7* K8* K10* K11* K13* K14* K16* K17* K19* K20* K22* K23* K25* K26* K31* K32* K34* K35*; U16 7(NC)*

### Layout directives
differential pair: D0_N, D0_P, D1_N, D1_P, D2_N, D2_P, D3_N, D3_P, D4_N, D4_P, D5_N, D5_P, D6_N, D6_P, D7_N, D7_P, DEVCLKARX_N, DEVCLKARX_P, DEVCLKBRX_N, DEVCLKBRX_P, FMC_DEVCLK_N, FMC_DEVCLK_P, FMC_SYSREF_N, FMC_SYSREF_P, SYNC_N, SYNC_P, SYSREFRX_N, SYSREFRX_P

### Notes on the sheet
- The D<7:0> connections polarity have been swapped from the TI standard FMC ADC guidelines to ease routing.  This is accounted for in the FPGA code.
- DP1_M2C_P
- DP1_M2C_N
- GBTCLK0_M2C_P
- DP2_M2C_P
- DP2_M2C_N
- DP0_M2C_P
- DP0_M2C_N
- GBTCLK0_M2C_N
- LA00_P_CC
- LA00_N_CC
- DP3_M2C_P
- DP3_M2C_N
- DP7_M2C_P
- DP7_M2C_N
- LA03_P
- LA03_N
- LA08_P
- LA08_N
- DP4_M2C_P
- DP4_M2C_N
- DP5_M2C_P
- DP6_M2C_P
- DP6_M2C_N
- DP5_M2C_N

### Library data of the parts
3P3RX VADJ_RX = 5011: Test Point, TH, Multipurpose, Black; Manufacturer: Keystone Electronics; CompType: Test Point Loop
C143 = C1608X5R1A105K: as C39 on sheet TSW12J64EVM_B_4_ADC_IO
FMC_RX1 = ASP-134488-01: Connector, Receptacle, 400-Pos (40x10), 50x50-mil Pitch, SMT; Manufacturer: Molex; Alternate PartNumber: 45970-4315; SymbolCreator: a0799721; U/M: EA
J1 = TSW-104-07-G-S: Header, TH, 100mil, 4x1, Gold plated, 230 mil above insulator; Manufacturer: Samtec, Inc.; SymbolCreator: a0412235; U/M: EA
KC705_JTAG PG_RX1 = TSW-102-07-G-S: as EXT_Vcmo on sheet TSW12J64EVM_B_4_ADC_IO
R132 = CRCW06030000Z0EA: RES, 0 ohm, 5%, 0.1W, 0603; Manufacturer: Vishay-Dale; CompType: Resistor; Value_Code: 0000; Tolerance_%: 5; Power_W: 0.1; VDC_V: 75; TempCo: 200 ppm/C; EIA_Code: E24; U/M: EA
RR6 = CRCW06034K99FKEA: RES, 4.99k ohm, 1%, 0.1W, 0603; Manufacturer: Vishay-Dale; CompType: Resistor; Res_ohm: 4990; Value_Code: 4k99; Tolerance_%: 1; Power_W: 0.1; VDC_V: 75; TempCo: 100 ppm/C; EIA_Code: E96; U/M: EA
RR7 = ERJ-3GEY0R00V: as R99 on sheet TSW12J64EVM_B_4_ADC_IO
U16 = 24C65T/SM: 64Kbit, 400kHz, 4.5V, I2C Serial EEPROM, 8-Pin SOIC 208mil, Commercial Temperature, Tape and Reel

## Sheet TSW12J64EVM_B_6_TRF3765.SchDoc
size 431 x 279 mm; Date: Not shown in title block; ApprovedBy: Not shown in title block; CheckedBy: Not shown in title block; Author: Not shown in title block; CompanyName: Not shown in title block; Engineer: Not shown in title block; Organization: Not shown in title block; Address1: Not shown in title block; Address2: Not shown in title block; Address3: Not shown in title block; Address4: Not shown in title block; DocumentNumber: 6; Revision: Use project parameter SCH_Rev; SheetNumber: 6; SheetTotal: 11; PageSetup: Record=PageOptions¦CenterHorizontal=True¦CenterVertical=True¦PrintScale=0.49¦XCorrection=1.00¦YCorrection=1.00¦PrintKind=0¦BorderSize=5000000¦LeftOffset=0¦BottomOffset=0¦Orientation=2¦PaperLength=1000¦PaperWidth=1000¦Scale=100¦PaperSource=15¦PrintQuality=600¦MediaType=1¦DitherType=10¦PaperKind=11x17¦PrintScaleMode=1
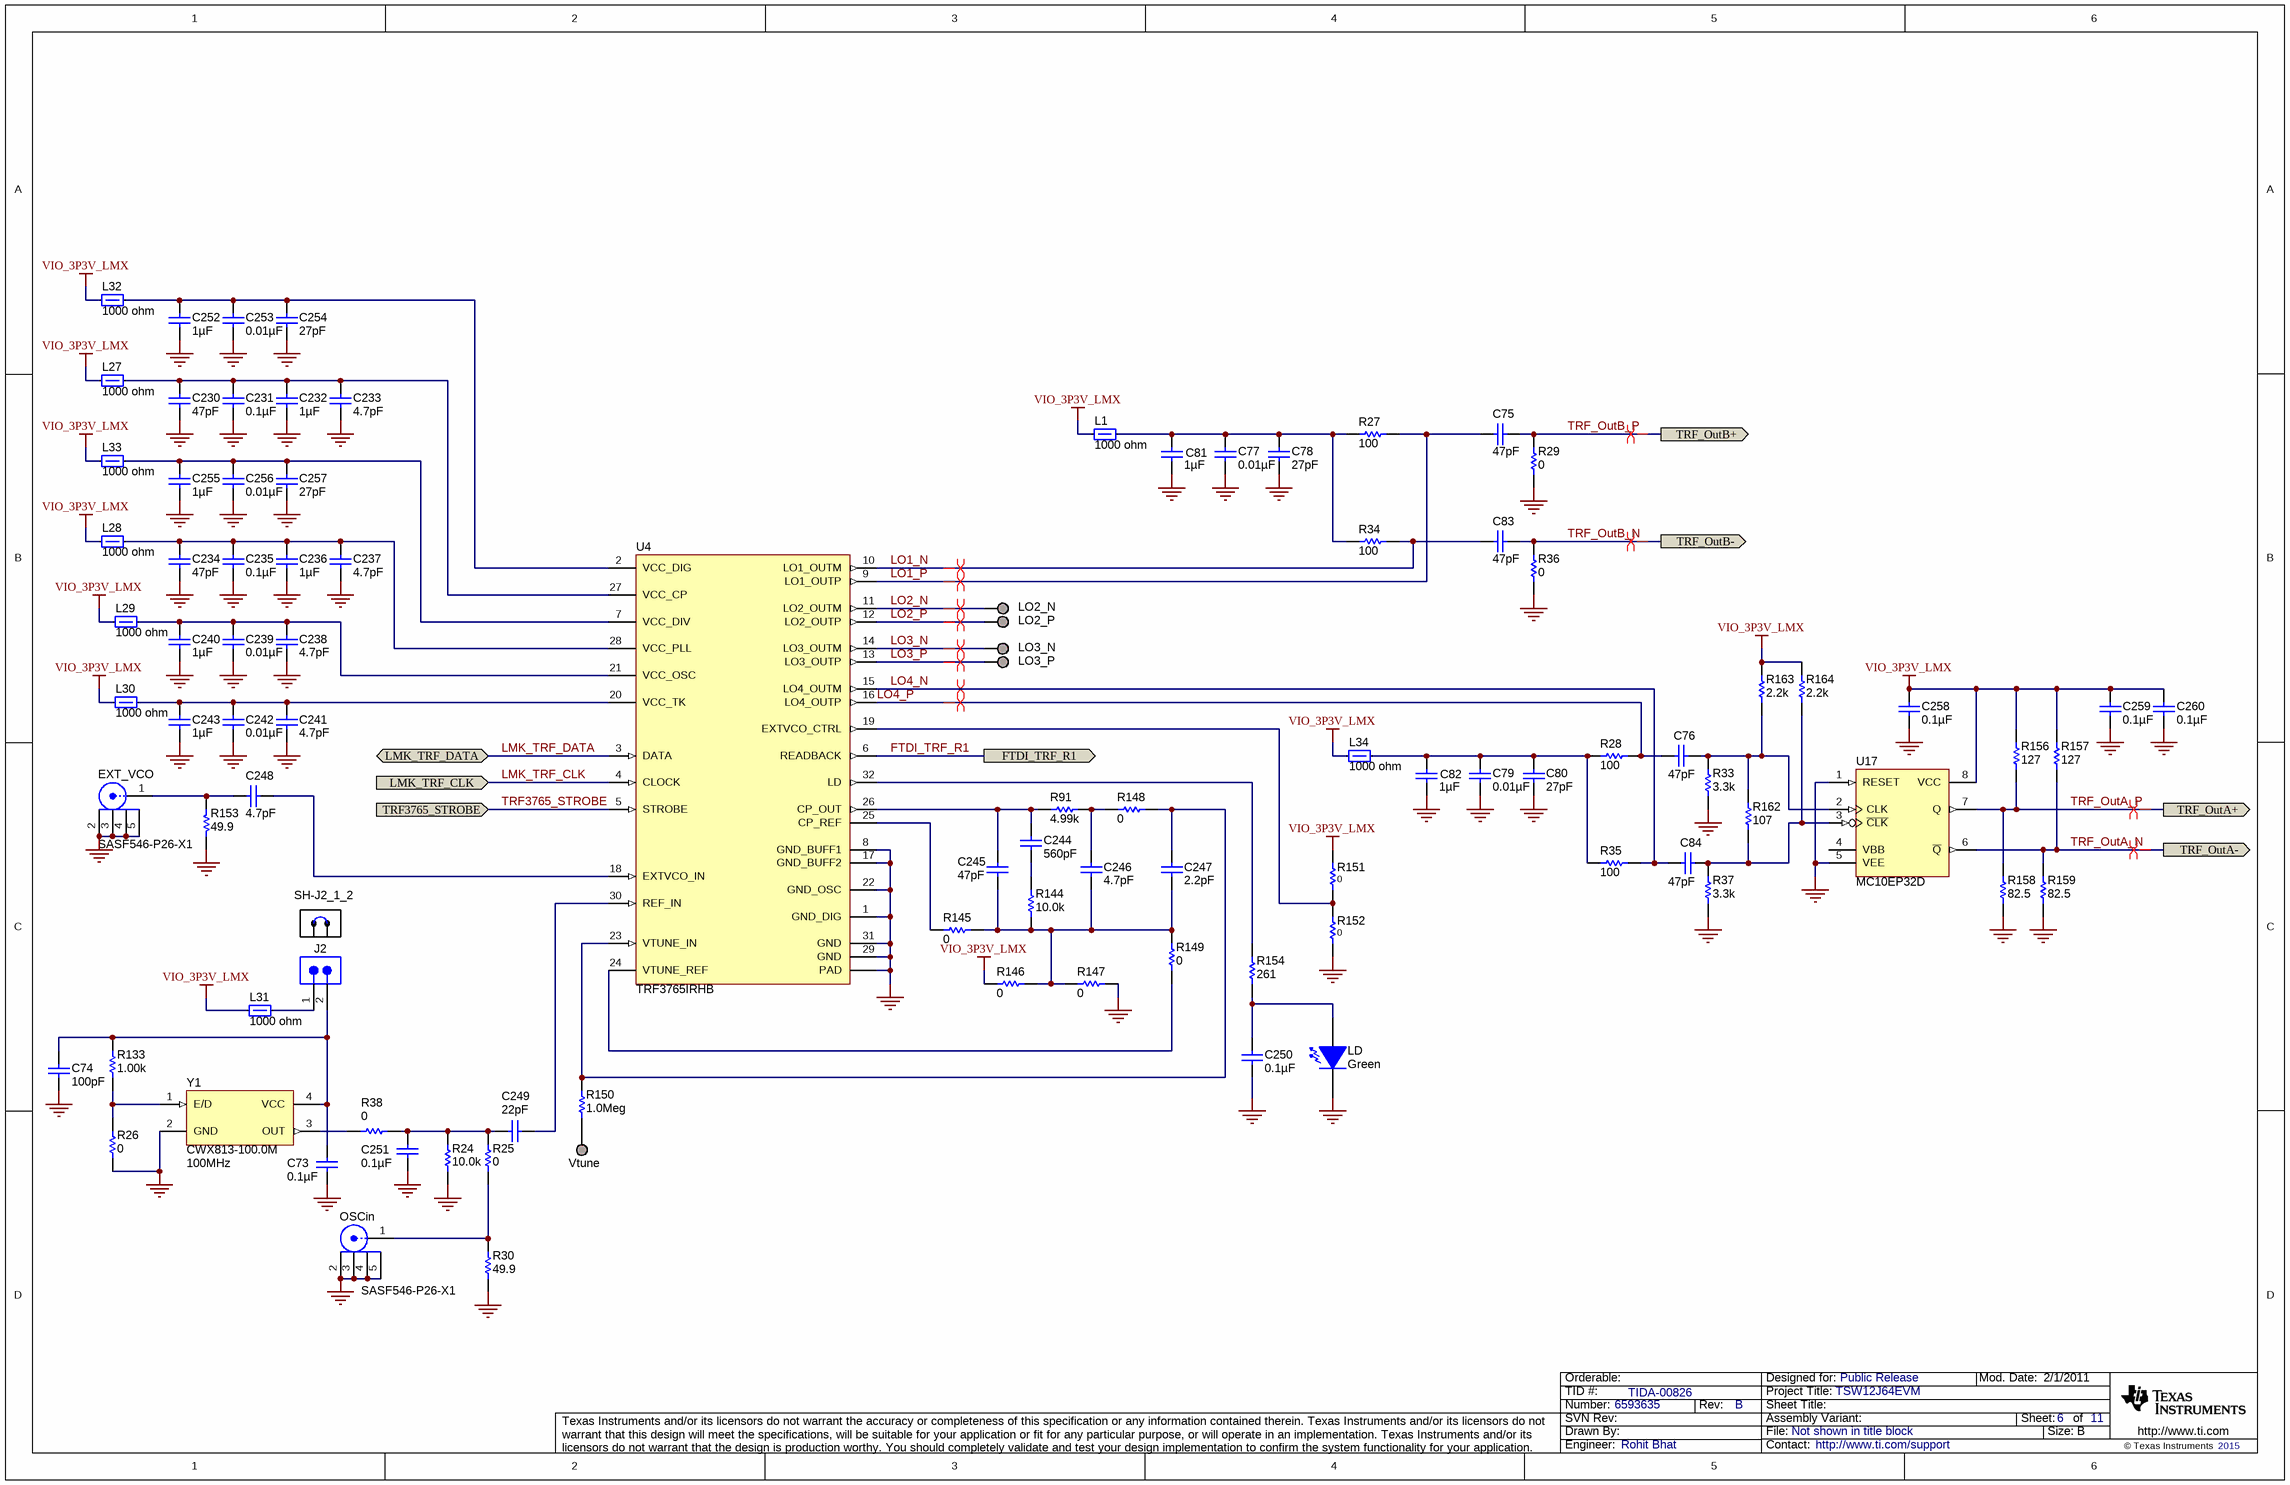
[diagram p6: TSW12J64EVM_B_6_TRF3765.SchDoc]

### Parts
C73  ValueDisplayed: 0.1µF  [0402L]  (hidden comment: C1005X5R1A104K)
C74  ValueDisplayed: 100pF  [0402L]  (hidden comment: GRM1555C1E101JA01D)
C75  ValueDisplayed: 47pF  [0402L]  (hidden comment: GRM1555C1H470JA01D)
C76  ValueDisplayed: 47pF  [0402L]  (hidden comment: GRM1555C1H470JA01D)
C77  ValueDisplayed: 0.01µF  [0402L]  (hidden comment: GRM155R71E103KA01D)
C78  ValueDisplayed: 27pF  [0402L]  (hidden comment: GRM1555C1H270JA01D)
C79  ValueDisplayed: 0.01µF  [0402L]  (hidden comment: GRM155R71E103KA01D)
C80  ValueDisplayed: 27pF  [0402L]  (hidden comment: GRM1555C1H270JA01D)
C81  ValueDisplayed: 1µF  [0402L]  (hidden comment: C1005X5R0J105M)
C82  ValueDisplayed: 1µF  [0402L]  (hidden comment: C1005X5R0J105M)
C83  ValueDisplayed: 47pF  [0402L]  (hidden comment: GRM1555C1H470JA01D)
C84  ValueDisplayed: 47pF  [0402L]  (hidden comment: GRM1555C1H470JA01D)
C230  ValueDisplayed: 47pF  [0603L]  (hidden comment: GRM1885C1H470JA01D)
C231  ValueDisplayed: 0.1µF  [0402L]  (hidden comment: C1005X5R1A104K)
C232  ValueDisplayed: 1µF  [0402L]  (hidden comment: C1005X5R0J105M)
C233  ValueDisplayed: 4.7pF  [0402L]  (hidden comment: GRM1555C1H4R7CA01D)
C234  ValueDisplayed: 47pF  [0603L]  (hidden comment: GRM1885C1H470JA01D)
C235  ValueDisplayed: 0.1µF  [0402L]  (hidden comment: C1005X5R1A104K)
C236  ValueDisplayed: 1µF  [0402L]  (hidden comment: C1005X5R0J105M)
C237  ValueDisplayed: 4.7pF  [0402L]  (hidden comment: GRM1555C1H4R7CA01D)
C238  ValueDisplayed: 4.7pF  [0402L]  (hidden comment: GRM1555C1H4R7CA01D)
C239  ValueDisplayed: 0.01µF  [0402L]  (hidden comment: GRM155R71E103KA01D)
C240  ValueDisplayed: 1µF  [0402L]  (hidden comment: C1005X5R0J105M)
C241  ValueDisplayed: 4.7pF  [0402L]  (hidden comment: GRM1555C1H4R7CA01D)
C242  ValueDisplayed: 0.01µF  [0402L]  (hidden comment: GRM155R71E103KA01D)
C243  ValueDisplayed: 1µF  [0402L]  (hidden comment: C1005X5R0J105M)
C244  ValueDisplayed: 560pF  [0402L]  (hidden comment: GRM1555C1H561JA01D)
C245  ValueDisplayed: 47pF  [0402L]  (hidden comment: GRM1555C1H470JA01D)
C246  ValueDisplayed: 4.7pF  [0402L]  (hidden comment: GRM1555C1H4R7CA01D)
C247  ValueDisplayed: 2.2pF  [0402L]  (hidden comment: GRM1555C1H2R2CA01D)
C248  ValueDisplayed: 4.7pF  [0402L]  (hidden comment: GRM1555C1H4R7CA01D)
C249  ValueDisplayed: 22pF  [0402L]  (hidden comment: GRM1555C1H220JA01D)
C250  ValueDisplayed: 0.1µF  [0402L]  (hidden comment: C1005X5R1A104K)
C251  ValueDisplayed: 0.1µF  [0402L]  (hidden comment: C1005X5R1A104K)
C252  ValueDisplayed: 1µF  [0402L]  (hidden comment: C1005X5R0J105M)
C253  ValueDisplayed: 0.01µF  [0402L]  (hidden comment: GRM155R71E103KA01D)
C254  ValueDisplayed: 27pF  [0402L]  (hidden comment: GRM1555C1H270JA01D)
C255  ValueDisplayed: 1µF  [0402L]  (hidden comment: C1005X5R0J105M)
C256  ValueDisplayed: 0.01µF  [0402L]  (hidden comment: GRM155R71E103KA01D)
C257  ValueDisplayed: 27pF  [0402L]  (hidden comment: GRM1555C1H270JA01D)
C258  ValueDisplayed: 0.1µF  [0402L]  (hidden comment: C1005X5R1A104K)
C259  ValueDisplayed: 0.1µF  [0402L]  (hidden comment: C1005X5R1A104K)
C260  ValueDisplayed: 0.1µF  [0402L]  (hidden comment: C1005X5R1A104K)
EXT_VCO  SASF546-P26-X1  [CONN_LTI_SASF546-P26-X1]
J2  TSW-102-07-G-S  [TSW-102-07-G-S]  (value not drawn)
L1  value 1000 ohm  [0402L]  (hidden comment: BLM15HG102SN1D)
L27  value 1000 ohm  [0402L]  (hidden comment: BLM15HG102SN1D)
L28  value 1000 ohm  [0402L]  (hidden comment: BLM15HG102SN1D)
L29  value 1000 ohm  [0402L]  (hidden comment: BLM15HG102SN1D)
L30  value 1000 ohm  [0402L]  (hidden comment: BLM15HG102SN1D)
L31  value 1000 ohm  [0402L]  (hidden comment: BLM15HG102SN1D)
L32  value 1000 ohm  [0402L]  (hidden comment: BLM15HG102SN1D)
L33  value 1000 ohm  [0402L]  (hidden comment: BLM15HG102SN1D)
L34  value 1000 ohm  [0402L]  (hidden comment: BLM15HG102SN1D)
LD  value Green  [LED_LTST-C190]  (hidden comment: LTST-C190GKT)
LO2_N  TESTPOINT  [TESTPOINT]  (value not drawn)  (no BOM)
LO2_P  TESTPOINT  [TESTPOINT]  (value not drawn)  (no BOM)
LO3_N  TESTPOINT  [TESTPOINT]  (value not drawn)  (no BOM)
LO3_P  TESTPOINT  [TESTPOINT]  (value not drawn)  (no BOM)
OSCin  SASF546-P26-X1  [CONN_LTI_SASF546-P26-X1]
R24  value 10.0k  [0402L]  (hidden comment: CRCW040210K0FKED)
R25  value 0  [0402L]  (hidden comment: ERJ-2GE0R00X)
R26  value 0  [0402L]  (hidden comment: ERJ-2GE0R00X)
R27  value 100  [0402L]  (hidden comment: CRCW0402100RFKED)
R28  value 100  [0402L]  (hidden comment: CRCW0402100RFKED)
R29  value 0  [0402L]  (hidden comment: ERJ-2GE0R00X)
R30  value 49.9  [0402L]  (hidden comment: CRCW040249R9FKED)
R33  value 3.3k  [0402L]  (hidden comment: CRCW04023K30JNED)
R34  value 100  [0402L]  (hidden comment: CRCW0402100RFKED)
R35  value 100  [0402L]  (hidden comment: CRCW0402100RFKED)
R36  value 0  [0402L]  (hidden comment: ERJ-2GE0R00X)
R37  value 3.3k  [0402L]  (hidden comment: CRCW04023K30JNED)
R38  value 0  [0402L]  (hidden comment: ERJ-2GE0R00X)
R91  value 4.99k  [0402L]  (hidden comment: CRCW04024K99FKED)
R133  value 1.00k  [0402L]  (hidden comment: CRCW04021K00FKED)
R144  value 10.0k  [0402L]  (hidden comment: CRCW040210K0FKED)
R145  value 0  [0402L]  (hidden comment: ERJ-2GE0R00X)
R146  value 0  [0402L]  (hidden comment: ERJ-2GE0R00X)
R147  value 0  [0402L]  (hidden comment: ERJ-2GE0R00X)
R148  value 0  [0402L]  (hidden comment: ERJ-2GE0R00X)
R149  value 0  [0402L]  (hidden comment: ERJ-2GE0R00X)
R150  value 1.0Meg  [0402L]  (hidden comment: CRCW04021M00JNED)
R151  value 0  [0603L]  (hidden comment: CRCW06030000Z0EA)
R152  value 0  [0603L]  (hidden comment: CRCW06030000Z0EA)
R153  value 49.9  [0402L]  (hidden comment: CRCW040249R9FKED)
R154  ValueDisplayed: 261  [0402L]  (hidden comment: CRCW0402261RFKED)
R156  value 127  [0402L]  (hidden comment: CRCW0402127RFKED)
R157  value 127  [0402L]  (hidden comment: CRCW0402127RFKED)
R158  value 82.5  [0402L]  (hidden comment: CRCW040282R5FKED)
R159  value 82.5  [0402L]  (hidden comment: CRCW040282R5FKED)
R162  value 107  [0402L]  (hidden comment: CRCW0402107RFKED)
R163  value 2.2k  [0402L]  (hidden comment: CRCW04022K20JNED)
R164  value 2.2k  [0402L]  (hidden comment: CRCW04022K20JNED)
SH-J2_1_2  SNT-100-BK-G  [SNT-100-BK-G]  (value not drawn)
U4  TRF3765IRHB  [RHB0032E]
U17  MC10EP32D  [751-06_N]
Vtune  TESTPOINT  [TESTPOINT]  (value not drawn)  (no BOM)
Y1  CWX813-100.0M  Frequency: 100MHz  [OSC_CWX]

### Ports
FTDI_TRF_R1, LMK_TRF_CLK, LMK_TRF_DATA (bidir), TRF3765_STROBE, TRF_OutA+ (out), TRF_OutA- (out), TRF_OutB+, TRF_OutB-

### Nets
GND: C73.1 C74.1 C77.2 C78.2 C79.2 C80.2 C81.2 C82.2 C230.2 C231.1 C232.2 C233.2 C234.2 C235.1 C236.2 C237.2 C238.2 C239.2 C240.2 C241.2 C242.2 C243.2 C250.1 C251.1 C252.2 C253.2 C254.2 C255.2 C256.2 C257.2 C258.1 C259.1 C260.1 EXT_VCO.2 EXT_VCO.3 EXT_VCO.4 EXT_VCO.5 LD.2(K) OSCin.2 OSCin.3 OSCin.4 OSCin.5 R24.1 R26.1 R29.1 R30.1 R33.1 R36.1 R37.1 R147.2 R152.2 R153.1 R158.1 R159.1 U4.1(GND_DIG) U4.8(GND_BUFF1) U4.17(GND_BUFF2) U4.22(GND_OSC) U4.29(GND) U4.31(GND) U4.33(PAD) U17.1(RESET) U17.5(VEE) Y1.2(GND)
VIO_3P3V_LMX: C258.2 C259.2 C260.2 L1.1 L27.1 L28.1 L29.1 L30.1 L31.1 L32.1 L33.1 L34.1 R146.1 R151.1 R156.2 R157.2 R163.2 R164.2 U17.8(VCC)
FTDI_TRF_R1: U4.6(READBACK) ; port FTDI_TRF_R1
LMK_TRF_CLK: U4.4(CLOCK) ; port LMK_TRF_CLK
LMK_TRF_DATA: U4.3(DATA) ; port LMK_TRF_DATA
LO1_N: C83.1 R34.2 U4.10(LO1_OUTM)
LO1_P: C75.1 R27.2 U4.9(LO1_OUTP)
LO2_N: LO2_N.1 U4.11(LO2_OUTM)
LO2_P: LO2_P.1 U4.12(LO2_OUTP)
LO3_N: LO3_N.1 U4.14(LO3_OUTM)
LO3_P: LO3_P.1 U4.13(LO3_OUTP)
LO4_N: C84.1 R35.2 U4.15(LO4_OUTM)
LO4_P: C76.1 R28.2 U4.16(LO4_OUTP)
TRF3765_STROBE: U4.5(STROBE) ; port TRF3765_STROBE
TRF_OutA_N: R157.1 R159.2 U17.6(~{Q}) ; port TRF_OutA-
TRF_OutA_P: R156.1 R158.2 U17.7(Q) ; port TRF_OutA+
TRF_OutB_N: C83.2 R36.2 ; port TRF_OutB-
TRF_OutB_P: C75.2 R29.2 ; port TRF_OutB+
NetC73_2: C73.2 C74.2 J2.2 R133.2 Y1.4(VCC)
NetC76_2: C76.2 R33.2 R162.2 R163.1 U17.2(CLK)
NetC77_1: C77.1 C78.1 C81.1 L1.2 R27.1 R34.1
NetC79_1: C79.1 C80.1 C82.1 L34.2 R28.1 R35.1
NetC84_2: C84.2 R37.2 R162.1 R164.1 U17.3(~{CLK})
NetC230_1: C230.1 C231.2 C232.1 C233.1 L27.2 U4.27(VCC_CP)
NetC234_1: C234.1 C235.2 C236.1 C237.1 L28.2 U4.28(VCC_PLL)
NetC238_1: C238.1 C239.1 C240.1 L29.2 U4.21(VCC_OSC)
NetC241_1: C241.1 C242.1 C243.1 L30.2 U4.20(VCC_TK)
NetC244_1: C244.1 C245.1 R91.1 U4.26(CP_OUT)
NetC244_2: C244.2 R144.2
NetC245_2: C245.2 C246.2 C247.2 R144.1 R145.2 R146.2 R147.1 R149.1
NetC246_1: C246.1 R91.2 R148.1
NetC247_1: C247.1 R148.2 R150.1 U4.23(VTUNE_IN)
NetC248_1: C248.1 U4.18(EXTVCO_IN)
NetC248_2: C248.2 EXT_VCO.1 R153.2
NetC249_1: C249.1 U4.30(REF_IN)
NetC249_2: C249.2 C251.2 R24.2 R25.2 R38.1
NetC250_2: C250.2 LD.1(A) R154.1
NetC252_1: C252.1 C253.1 C254.1 L32.2 U4.2(VCC_DIG)
NetC255_1: C255.1 C256.1 C257.1 L33.2 U4.7(VCC_DIV)
NetJ2_1: J2.1 L31.2
NetOSCin_1: OSCin.1 R25.1 R30.2
NetR26_2: R26.2 R133.1 Y1.1(E/D)
NetR38_2: R38.2 Y1.3(OUT)
NetR145_1: R145.1 U4.25(CP_REF)
NetR149_2: R149.2 U4.24(VTUNE_REF)
NetR150_2: R150.2 Vtune.1
NetR151_2: R151.2 R152.1 U4.19(EXTVCO_CTRL)
NetR154_2: R154.2 U4.32(LD)

Not connected (* = marked no-connect by the designer): U17 4(VBB)

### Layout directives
differential pair: LO1_N, LO1_P, LO2_N, LO2_P, LO3_N, LO3_P, LO4_N, LO4_P, TRF_OutA_N, TRF_OutA_P, TRF_OutB_N, TRF_OutB_P

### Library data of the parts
C73 C231 C235 C250 C251 C258-C260 = C1005X5R1A104K: as C18 on sheet TSW12J64EVM_B_4_ADC_IO
C74 = GRM1555C1E101JA01D: CAP, CERM, 100pF, 25V, +/-5%, C0G/NP0, 0402; Manufacturer: MuRata; Cap_Case: 0402; Polarized: N; TaMax_C: 125; TaMin_C: -55; Tolerance_%: 5; VDC_V: 25; Cap_F: 0.0000000001; CompType: Capacitor; U/M: EA
C75 C76 C83 C84 C245 = GRM1555C1H470JA01D: CAP, CERM, 47pF, 50V, +/-5%, C0G/NP0, 0402; Manufacturer: MuRata; Polarized: N; CompType: Capacitor; U/M: EA; Cap_F: 0.000000000047; Tolerance_%: 5; Value1: Unknown; VDC_V: 50; TaMin_C: -55; TaMax_C: 125; Cap_Case: 0402
C77 C79 C239 C242 C253 C256 = GRM155R71E103KA01D: CAP, CERM, 0.01uF, 25V, +/-10%, X7R, 0402; Manufacturer: MuRata; Polarized: N; CompType: Capacitor; U/M: EA; Cap_F: 0.00000001; Tolerance_%: 10; Value1: Unknown; VDC_V: 25; TaMin_C: -55; TaMax_C: 125; Cap_Case: 0402
C78 C80 C254 C257 = GRM1555C1H270JA01D: CAP, CERM, 27pF, 50V, +/-5%, C0G/NP0, 0402; Manufacturer: MuRata; Polarized: N; CompType: Capacitor; U/M: EA; Cap_F: 0.000000000027; Tolerance_%: 5; Value1: Unknown; VDC_V: 50; TaMin_C: -55; TaMax_C: 125; Cap_Case: 0402
C81 C82 C232 C236 C240 C243 C252 C255 = C1005X5R0J105M: CAP, CERM, 1uF, 6.3V, +/-20%, X5R, 0402; Manufacturer: TDK; Polarized: N; CompType: Capacitor; U/M: EA; Cap_F: 0.000001; Tolerance_%: 20; ESR_Ohm: 0.0079; Value1: 0.0079 ohm; VDC_V: 6.3; TaMin_C: -55; TaMax_C: 85; Cap_Case: 0402
C230 C234 = GRM1885C1H470JA01D: CAP, CERM, 47pF, 50V, +/-5%, C0G/NP0, 0603; Manufacturer: MuRata; Polarized: N; CompType: Capacitor; U/M: EA; Cap_F: 0.000000000047; Tolerance_%: 5; Value1: Unknown; VDC_V: 50; TaMin_C: -55; TaMax_C: 125; Cap_Case: 0603
C233 C237 C238 C241 C246 C248 = GRM1555C1H4R7CA01D: CAP, CERM, 4.7pF, 50V, +/-5%, C0G/NP0, 0402; Manufacturer: MuRata; Polarized: N; CompType: Capacitor; U/M: EA; Cap_F: 0.0000000000047; Tolerance_%: 5; Value1: Unknown; VDC_V: 50; TaMin_C: -55; TaMax_C: 125; Cap_Case: 0402
C244 = GRM1555C1H561JA01D: CAP, CERM, 560pF, 50V, +/-5%, C0G/NP0, 0402; Manufacturer: MuRata; Polarized: N; CompType: Capacitor; U/M: EA; Cap_F: 0.00000000056; Tolerance_%: 5; Value1: Unknown; VDC_V: 50; TaMin_C: -55; TaMax_C: 125; Cap_Case: 0402
C247 = GRM1555C1H2R2CA01D: CAP, CERM, 2.2pF, 50V, +/-5%, C0G/NP0, 0402; Manufacturer: MuRata; Polarized: N; CompType: Capacitor; U/M: EA; Cap_F: 0.0000000000022; Tolerance_%: 5; Value1: Unknown; VDC_V: 50; TaMin_C: -55; TaMax_C: 125; Cap_Case: 0402
C249 = GRM1555C1H220JA01D: CAP, CERM, 22pF, 50V, +/-5%, C0G/NP0, 0402; Manufacturer: MuRata; Polarized: N; CompType: Capacitor; U/M: EA; Cap_F: 0.000000000022; Tolerance_%: 5; Value1: Unknown; VDC_V: 50; TaMin_C: -55; TaMax_C: 125; Cap_Case: 0402
EXT_VCO OSCin = SASF546-P26-X1: as DEVCLK on sheet TSW12J64EVM_B_4_ADC_IO
J2 = TSW-102-07-G-S: as EXT_Vcmo on sheet TSW12J64EVM_B_4_ADC_IO
L1 L27-L34 = BLM15HG102SN1D: 0.25A Ferrite Bead, 1000 ohm @ 100MHz, SMD; Manufacturer: MuRata; Imax_A: 0.25; Irms: 0.25A @ C rise; Isat: 0.25A @ % inductance drop; DCR_ohm: 1.1; Value1: 1.1 ohm; ZTyp@100MHz_Ohm: 1000; U/M: EA
LD = LTST-C190GKT: LED, Green, SMD; Manufacturer: Lite-On; Vf_V: 2.1; Value2: 2.1V; Io_A: 0.02; Power_TotalModule: 0.1; Value1: 0.1W; U/M: EA
LO2_N LO2_P LO3_N LO3_P Vtune = TESTPOINT: TEST POINT.  No entry in BOM.
R24 R144 = CRCW040210K0FKED: RES, 10.0k ohm, 1%, 0.063W, 0402; Manufacturer: Vishay-Dale; CompType: Resistor; Res_ohm: 10000; Value_Code: 10k0; Tolerance_%: 1; Power_W: 0.063; VDC_V: 50; TempCo: 100 ppm/C; EIA_Code: E96; U/M: EA
R25 R26 R29 R36 R38 R145-R149 = ERJ-2GE0R00X: RES, 0 ohm, 5%, 0.063W, 0402; Manufacturer: Panasonic; CompType: Resistor; Value_Code: 0000; Tolerance_%: 5; Power_W: 0.063; VDC_V: 50; TempCo: 600 ppm/C; EIA_Code: E24; U/M: EA
R27 R28 R34 R35 = CRCW0402100RFKED: RES, 100 ohm, 1%, 0.063W, 0402; Manufacturer: Vishay-Dale; CompType: Resistor; Value_Code: 100R; Tolerance_%: 1; Power_W: 0.063; VDC_V: 50; TempCo: 100 ppm/C; EIA_Code: E96; U/M: EA
R30 R153 = CRCW040249R9FKED: RES, 49.9 ohm, 1%, 0.063W, 0402; Manufacturer: Vishay-Dale; CompType: Resistor; Value_Code: 49R9; Tolerance_%: 1; Power_W: 0.063; VDC_V: 50; TempCo: 100 ppm/C; EIA_Code: E96; U/M: EA
R33 R37 = CRCW04023K30JNED: RES, 3.3k ohm, 5%, 0.063W, 0402; Manufacturer: Vishay-Dale; CompType: Resistor; Res_ohm: 3300; Value_Code: 3k30; Tolerance_%: 5; Power_W: 0.063; VDC_V: 50; TempCo: 200 ppm/C; EIA_Code: E24; U/M: EA
R91 = CRCW04024K99FKED: RES, 4.99k ohm, 1%, 0.063W, 0402; Manufacturer: Vishay-Dale; CompType: Resistor; Res_ohm: 4990; Value_Code: 4k99; Tolerance_%: 1; Power_W: 0.063; VDC_V: 50; TempCo: 100 ppm/C; EIA_Code: E96; U/M: EA
R133 = CRCW04021K00FKED: RES, 1.00k ohm, 1%, 0.063W, 0402; Manufacturer: Vishay-Dale; CompType: Resistor; Res_ohm: 1000; Value_Code: 1k00; Tolerance_%: 1; Power_W: 0.063; VDC_V: 50; TempCo: 100 ppm/C; EIA_Code: E96; U/M: EA
R150 = CRCW04021M00JNED: as R3 on sheet TSW12J64EVM_B_4_ADC_IO
R151 R152 = CRCW06030000Z0EA: RES, 0 ohm, 5%, 0.1W, 0603; Manufacturer: Vishay-Dale; CompType: Resistor; Tolerance_%: 5; VDC_V: 75; Power_W: 0.1; U/M: EA; Value_Code: 0000; EIA_Code: E24
R154 = CRCW0402261RFKED: RES, 261, 1%, 0.063 W, 0402; Manufacturer: Vishay-Dale; CompType: Resistor; Value: 261; Value_Code: 261R; Tolerance_%: 1; Power_W: 0.063; Value2: 0.063W; VDC_V: 50; TempCo: 100 ppm/C; EIA_Code: E96; U/M: EA
R156 R157 = CRCW0402127RFKED: RES, 127 ohm, 1%, 0.063W, 0402; Manufacturer: Vishay-Dale; CompType: Resistor; Value_Code: 127R; Tolerance_%: 1; Power_W: 0.063; VDC_V: 50; TempCo: 100 ppm/C; EIA_Code: E96; U/M: EA
R158 R159 = CRCW040282R5FKED: RES, 82.5 ohm, 1%, 0.063W, 0402; Manufacturer: Vishay-Dale; CompType: Resistor; Value_Code: 82R5; Tolerance_%: 1; Power_W: 0.063; VDC_V: 50; TempCo: 100 ppm/C; EIA_Code: E96; U/M: EA
R162 = CRCW0402107RFKED: RES, 107 ohm, 1%, 0.063W, 0402; Manufacturer: Vishay-Dale; CompType: Resistor; Value_Code: 107R; Tolerance_%: 1; Power_W: 0.063; VDC_V: 50; TempCo: 100 ppm/C; EIA_Code: E96; U/M: EA
R163 R164 = CRCW04022K20JNED: RES, 2.2k ohm, 5%, 0.063W, 0402; Manufacturer: Vishay-Dale; CompType: Resistor; Res_ohm: 2200; Value_Code: 2k20; Tolerance_%: 5; Power_W: 0.063; VDC_V: 50; TempCo: 200 ppm/C; EIA_Code: E24; U/M: EA
SH-J2_1_2 = SNT-100-BK-G: as SH-RSV_1_2 on sheet TSW12J64EVM_B_4_ADC_IO
U4 = TRF3765IRHB: Integer-N/Fractional-N PLL with Integrated VCO, RHB0032E; Alternate Manufacturer: None; Manufacturer: Texas Instruments; SymbolCreator: x0208326; CompType: IC; U/M: EA
U17 = MC10EP32D: Divide-by-2 Divider; Manufacturer: ON Semiconductor; PartNumber: MC10EP32DG
Y1 = CWX813-100.0M: OSC 100.0000MHZ 3.3V +-25PPM SMD; Manufacturer: Connor-Winfield; SymbolCreator: a0411947; CompType: Crystal; U/M: EA; TaMin_C: -20; TaMax_C: 70; Frequency Stability: ±25ppm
